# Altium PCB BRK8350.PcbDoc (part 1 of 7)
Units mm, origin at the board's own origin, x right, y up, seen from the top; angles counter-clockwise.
Board outline 240 x 150 mm, 8 copper layers (L1-TOP, L2-GND, L3-PWR, L4-SIG, L5-SIG, L6-PWR, L7-GND, L8-BOT), stack 1.465 mm thick; 277 components, 542 nets, 1814 pads, 2338 vias.
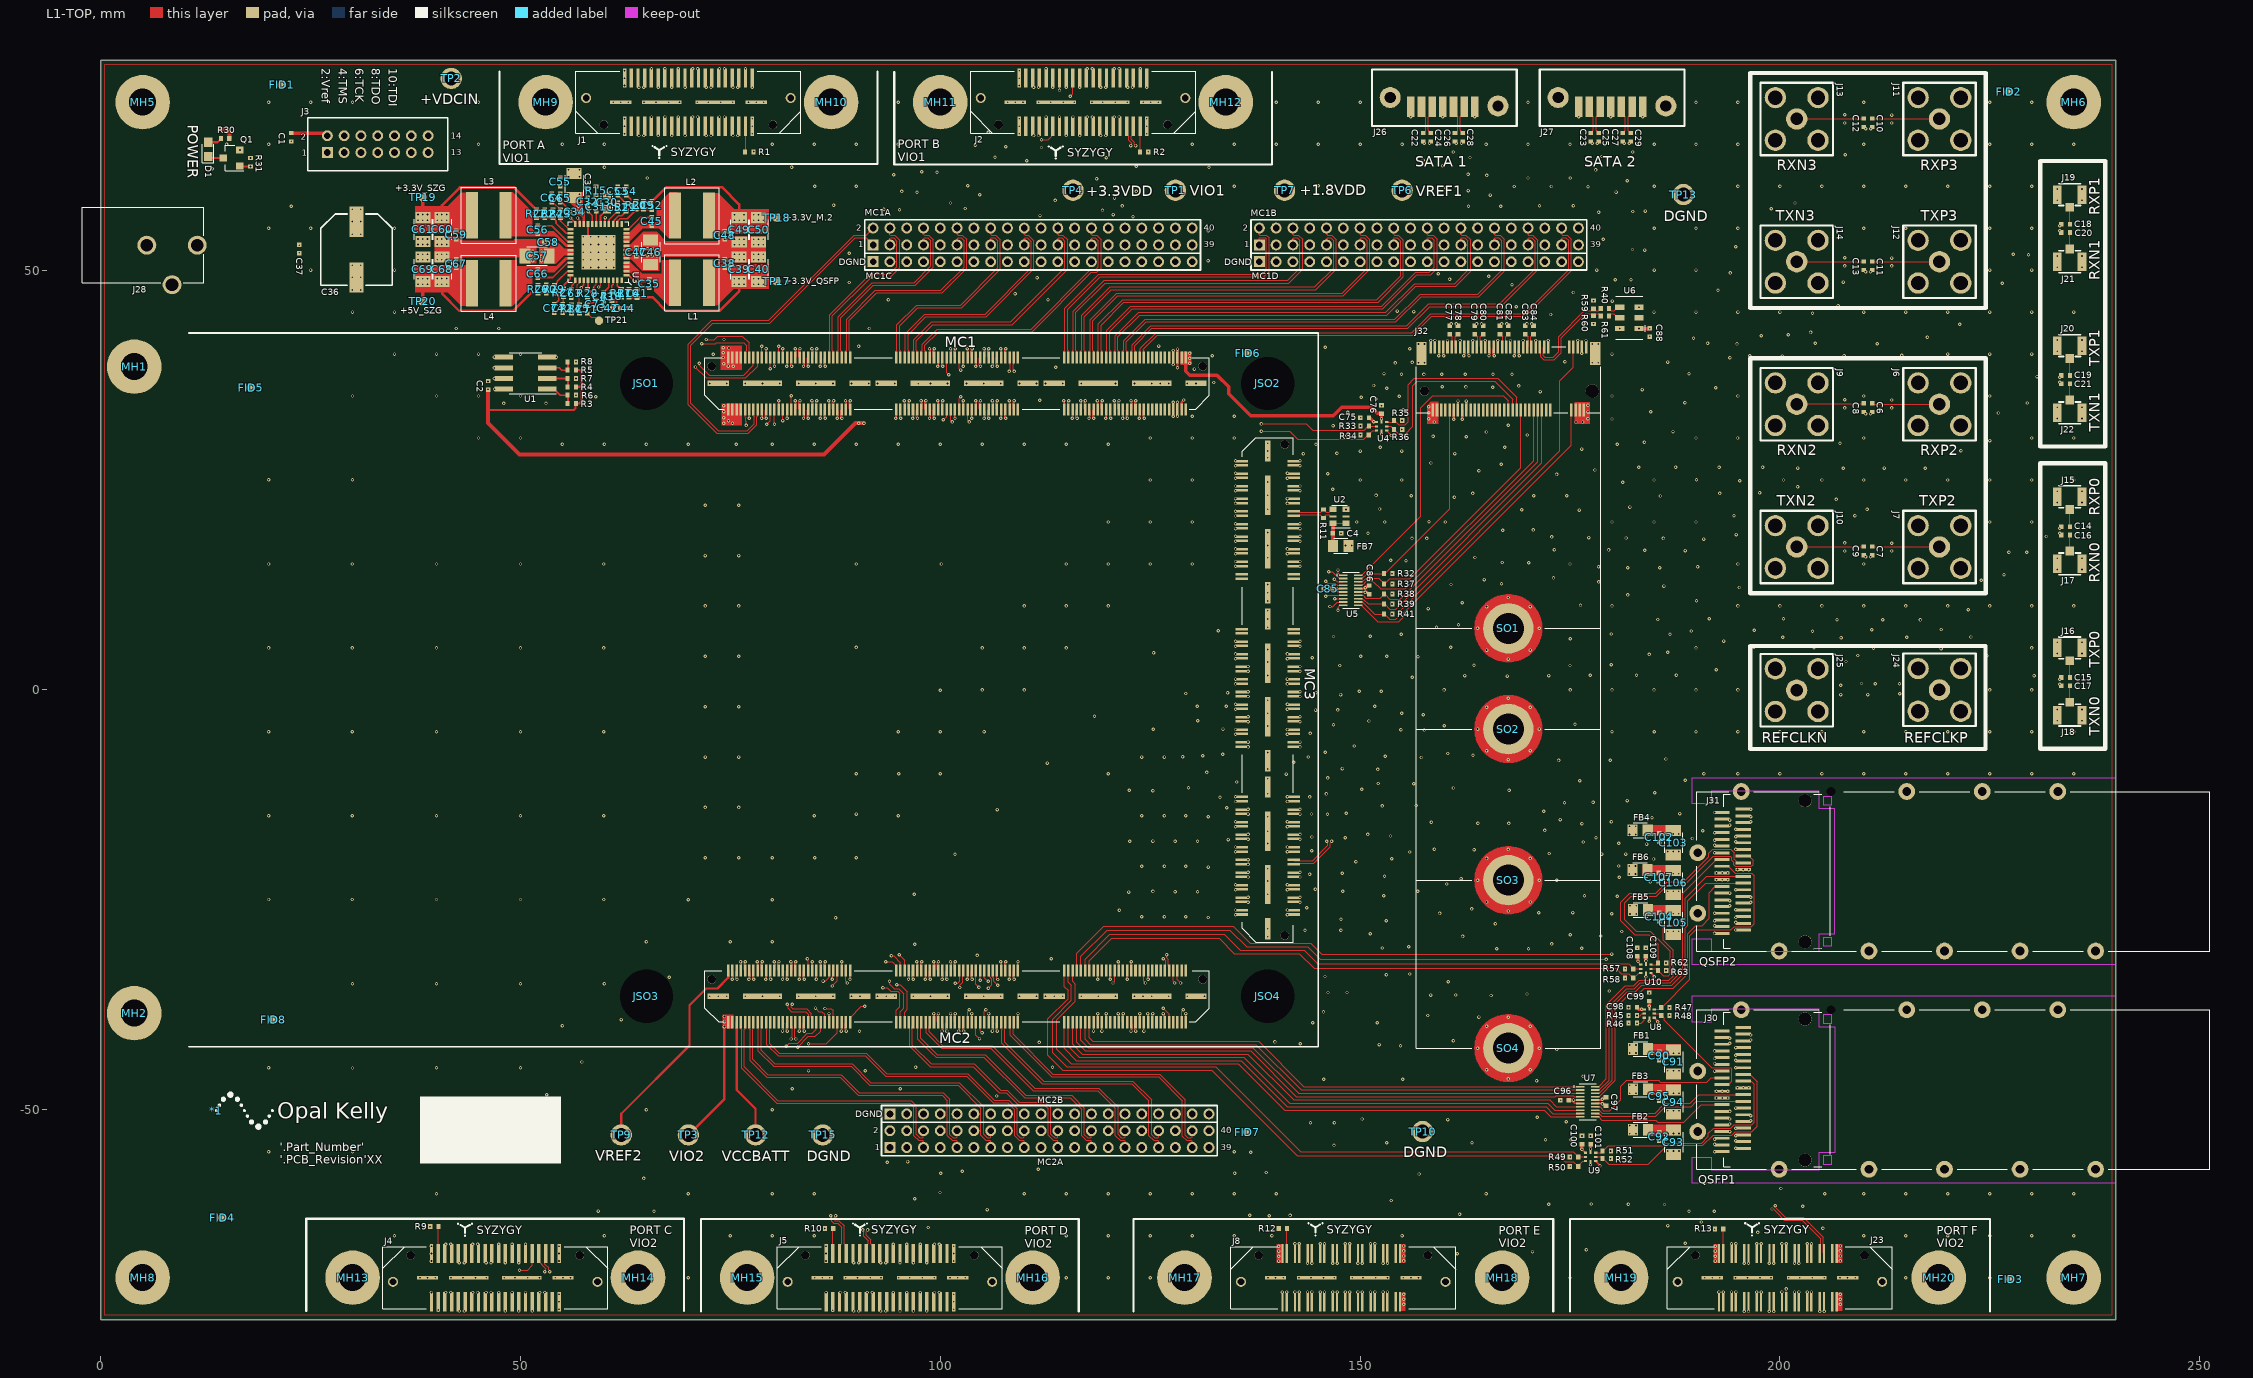
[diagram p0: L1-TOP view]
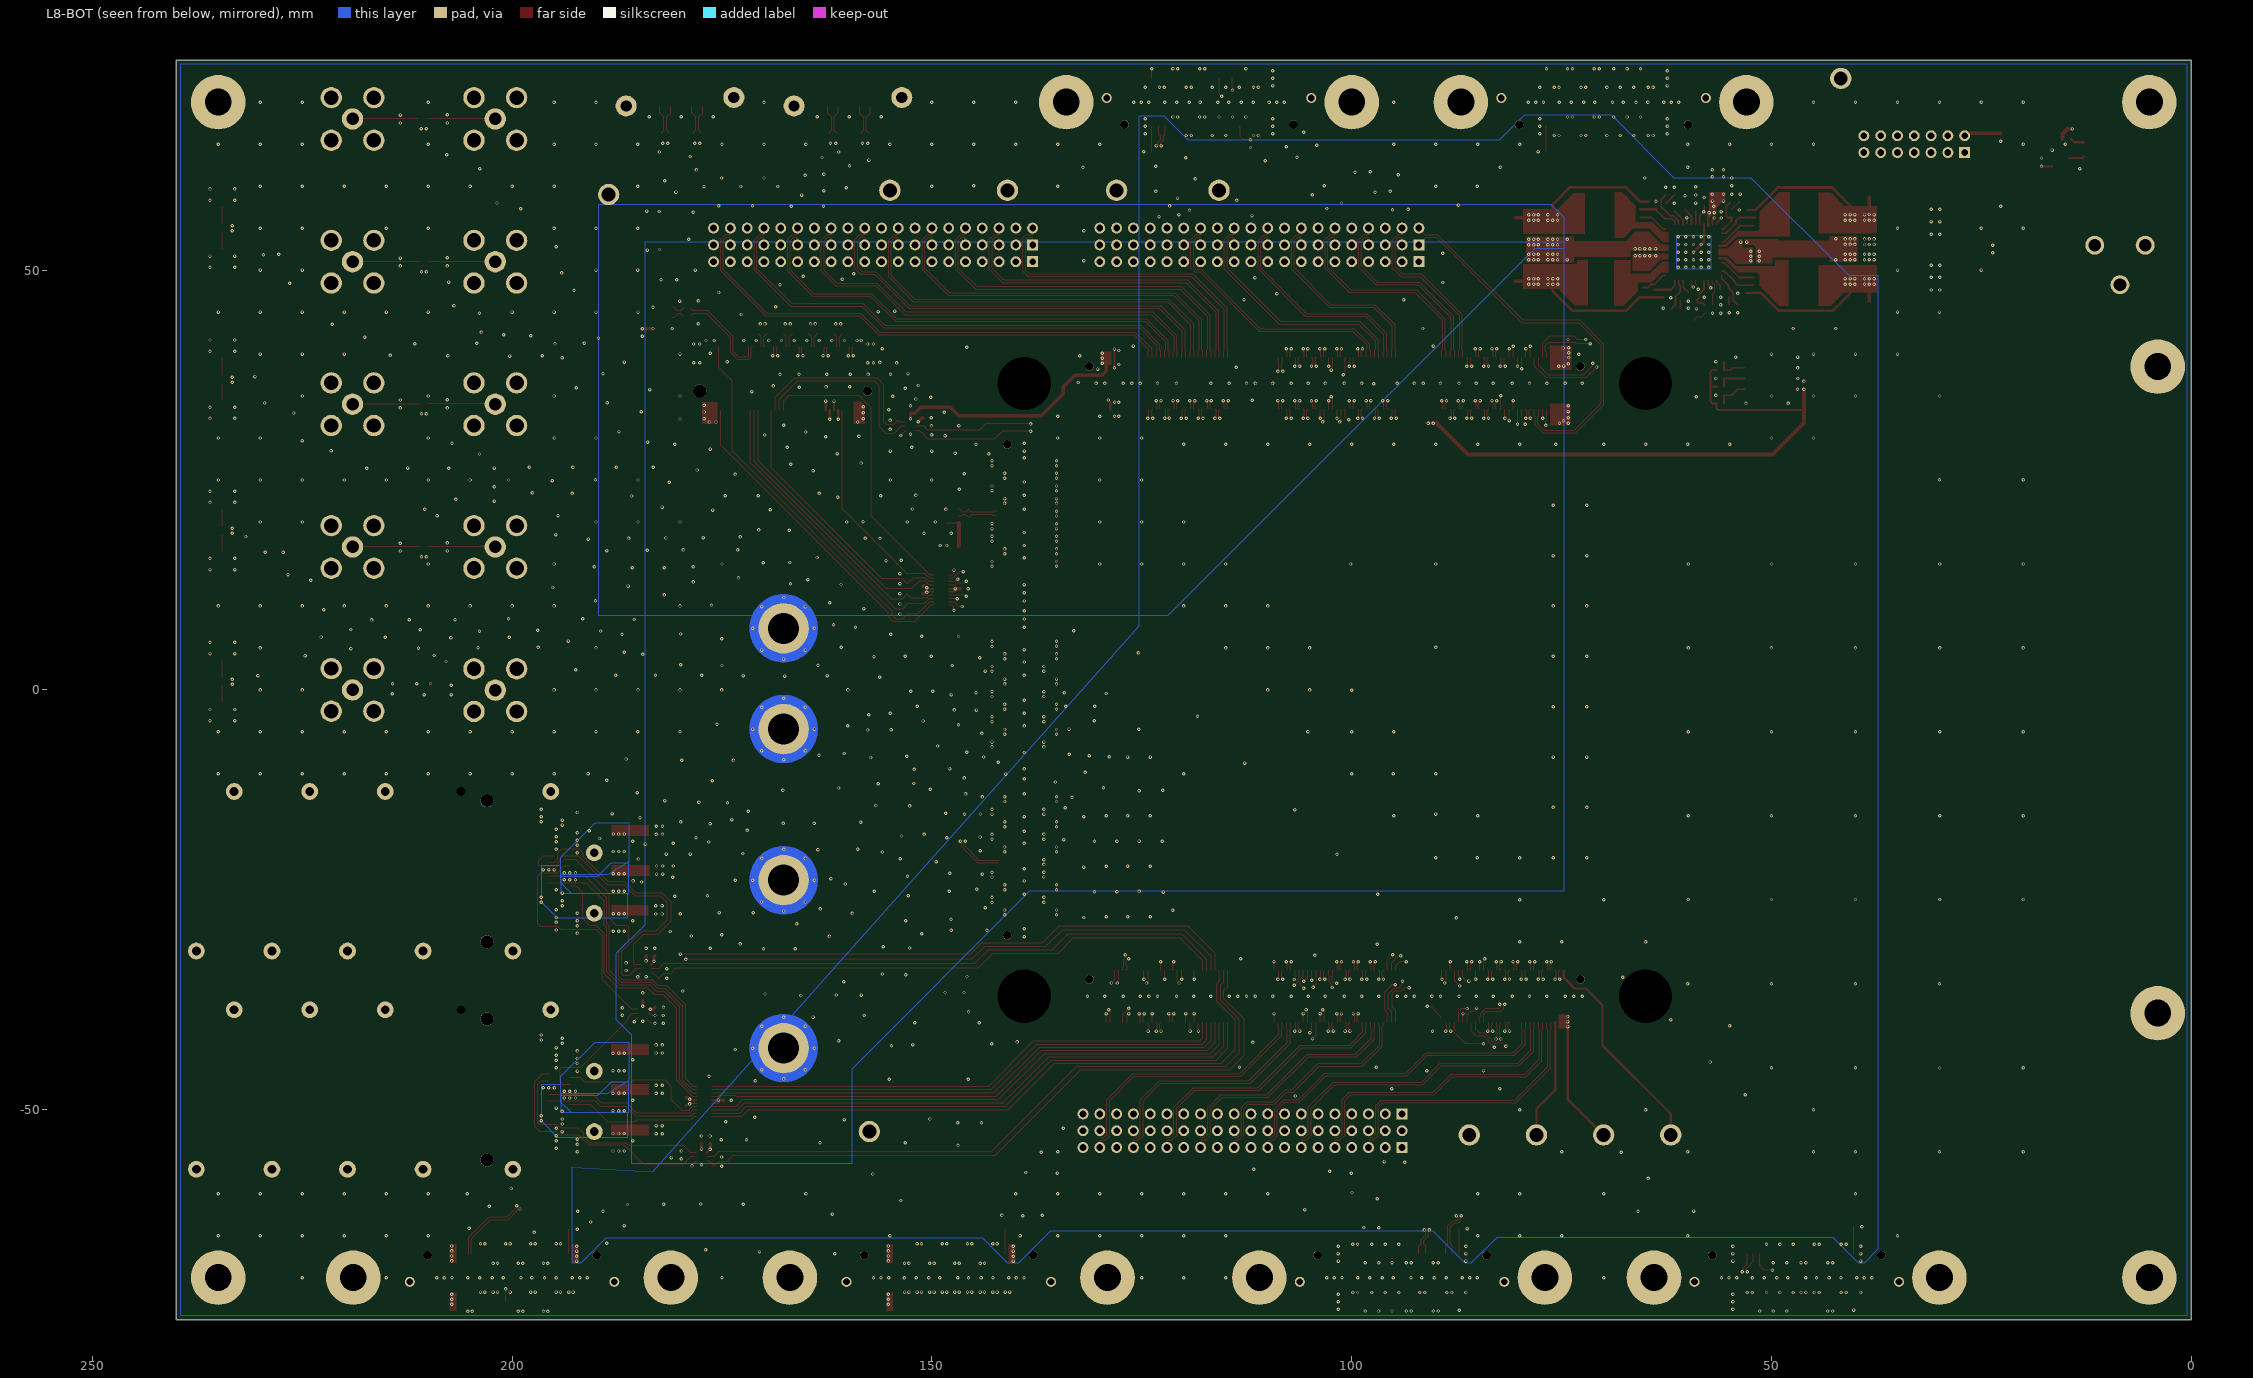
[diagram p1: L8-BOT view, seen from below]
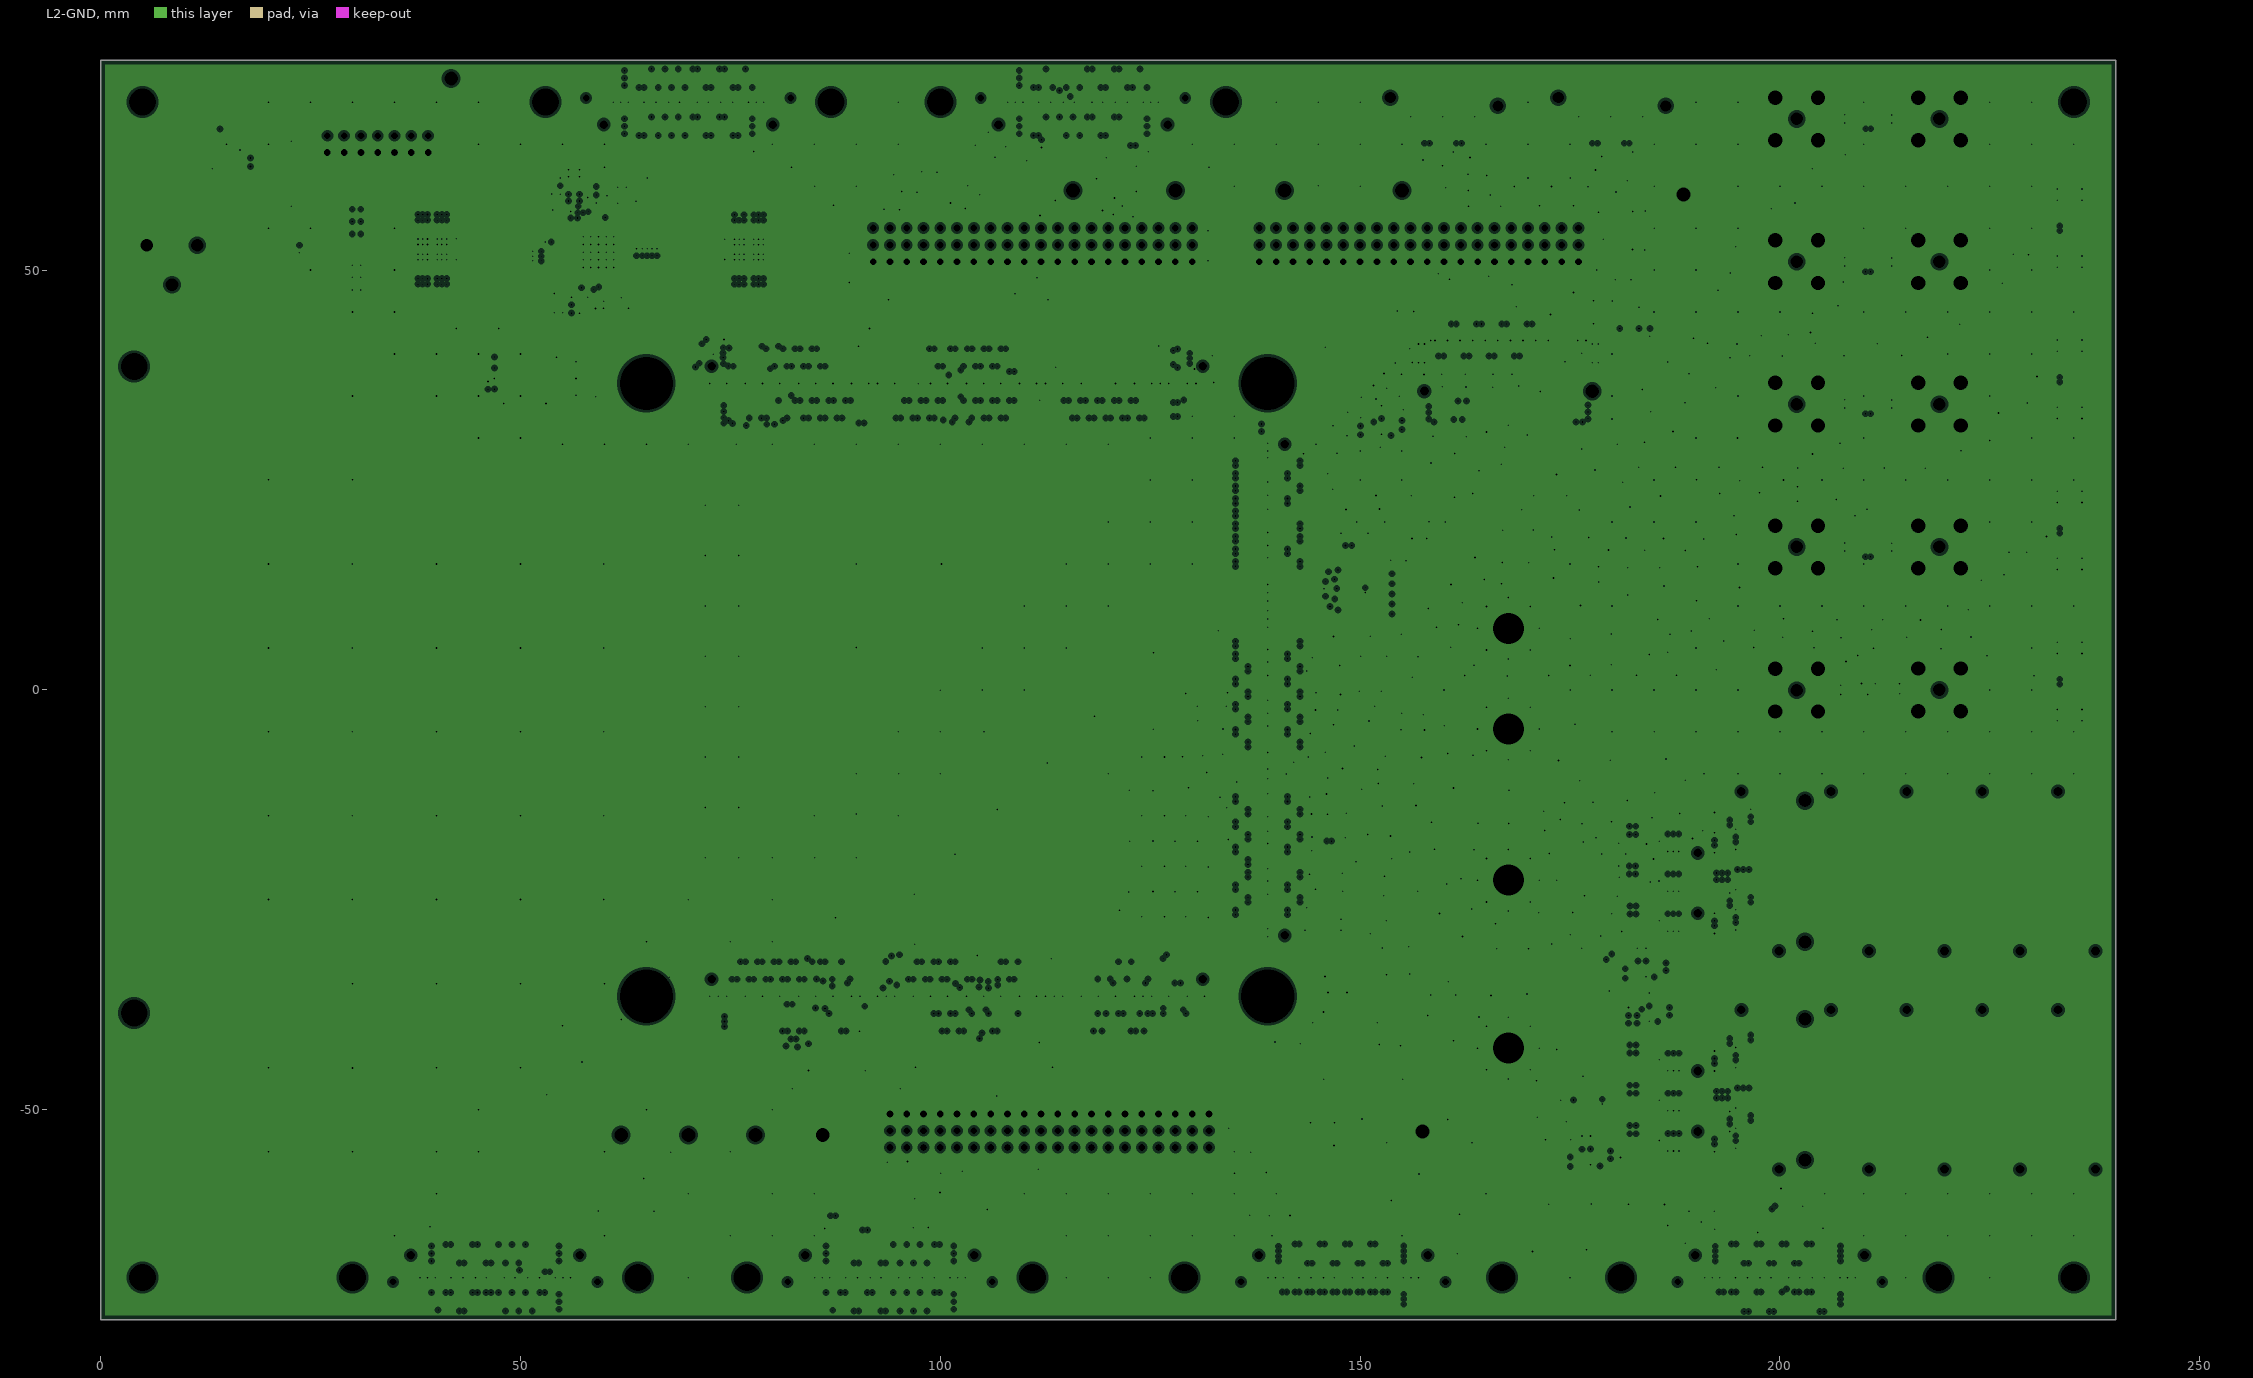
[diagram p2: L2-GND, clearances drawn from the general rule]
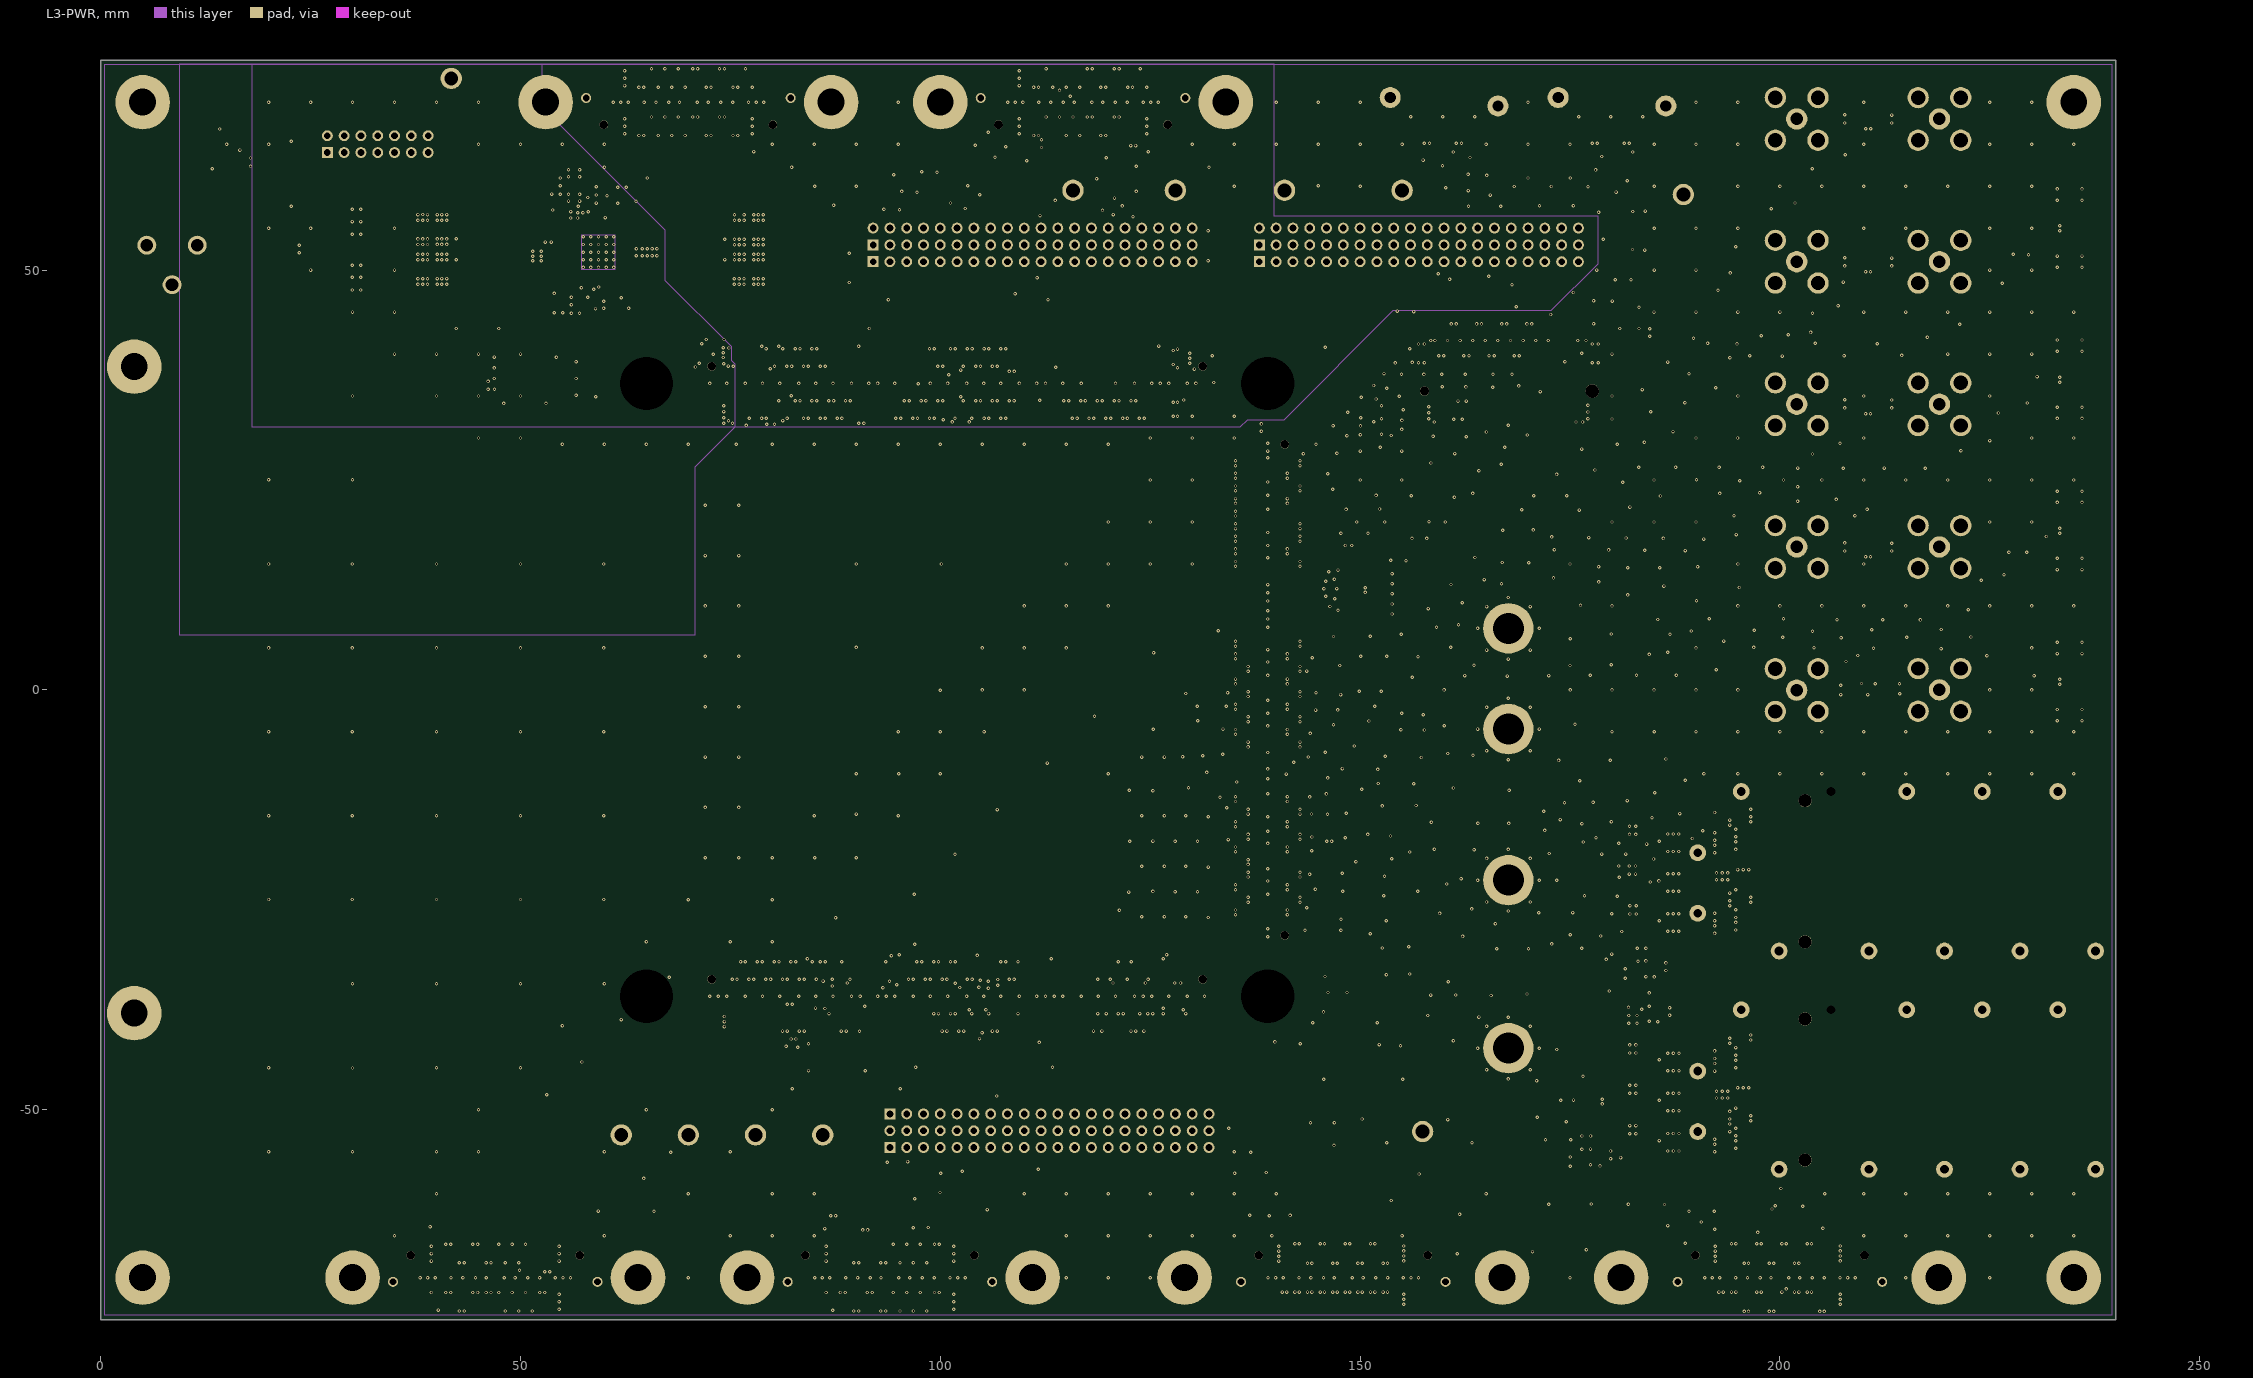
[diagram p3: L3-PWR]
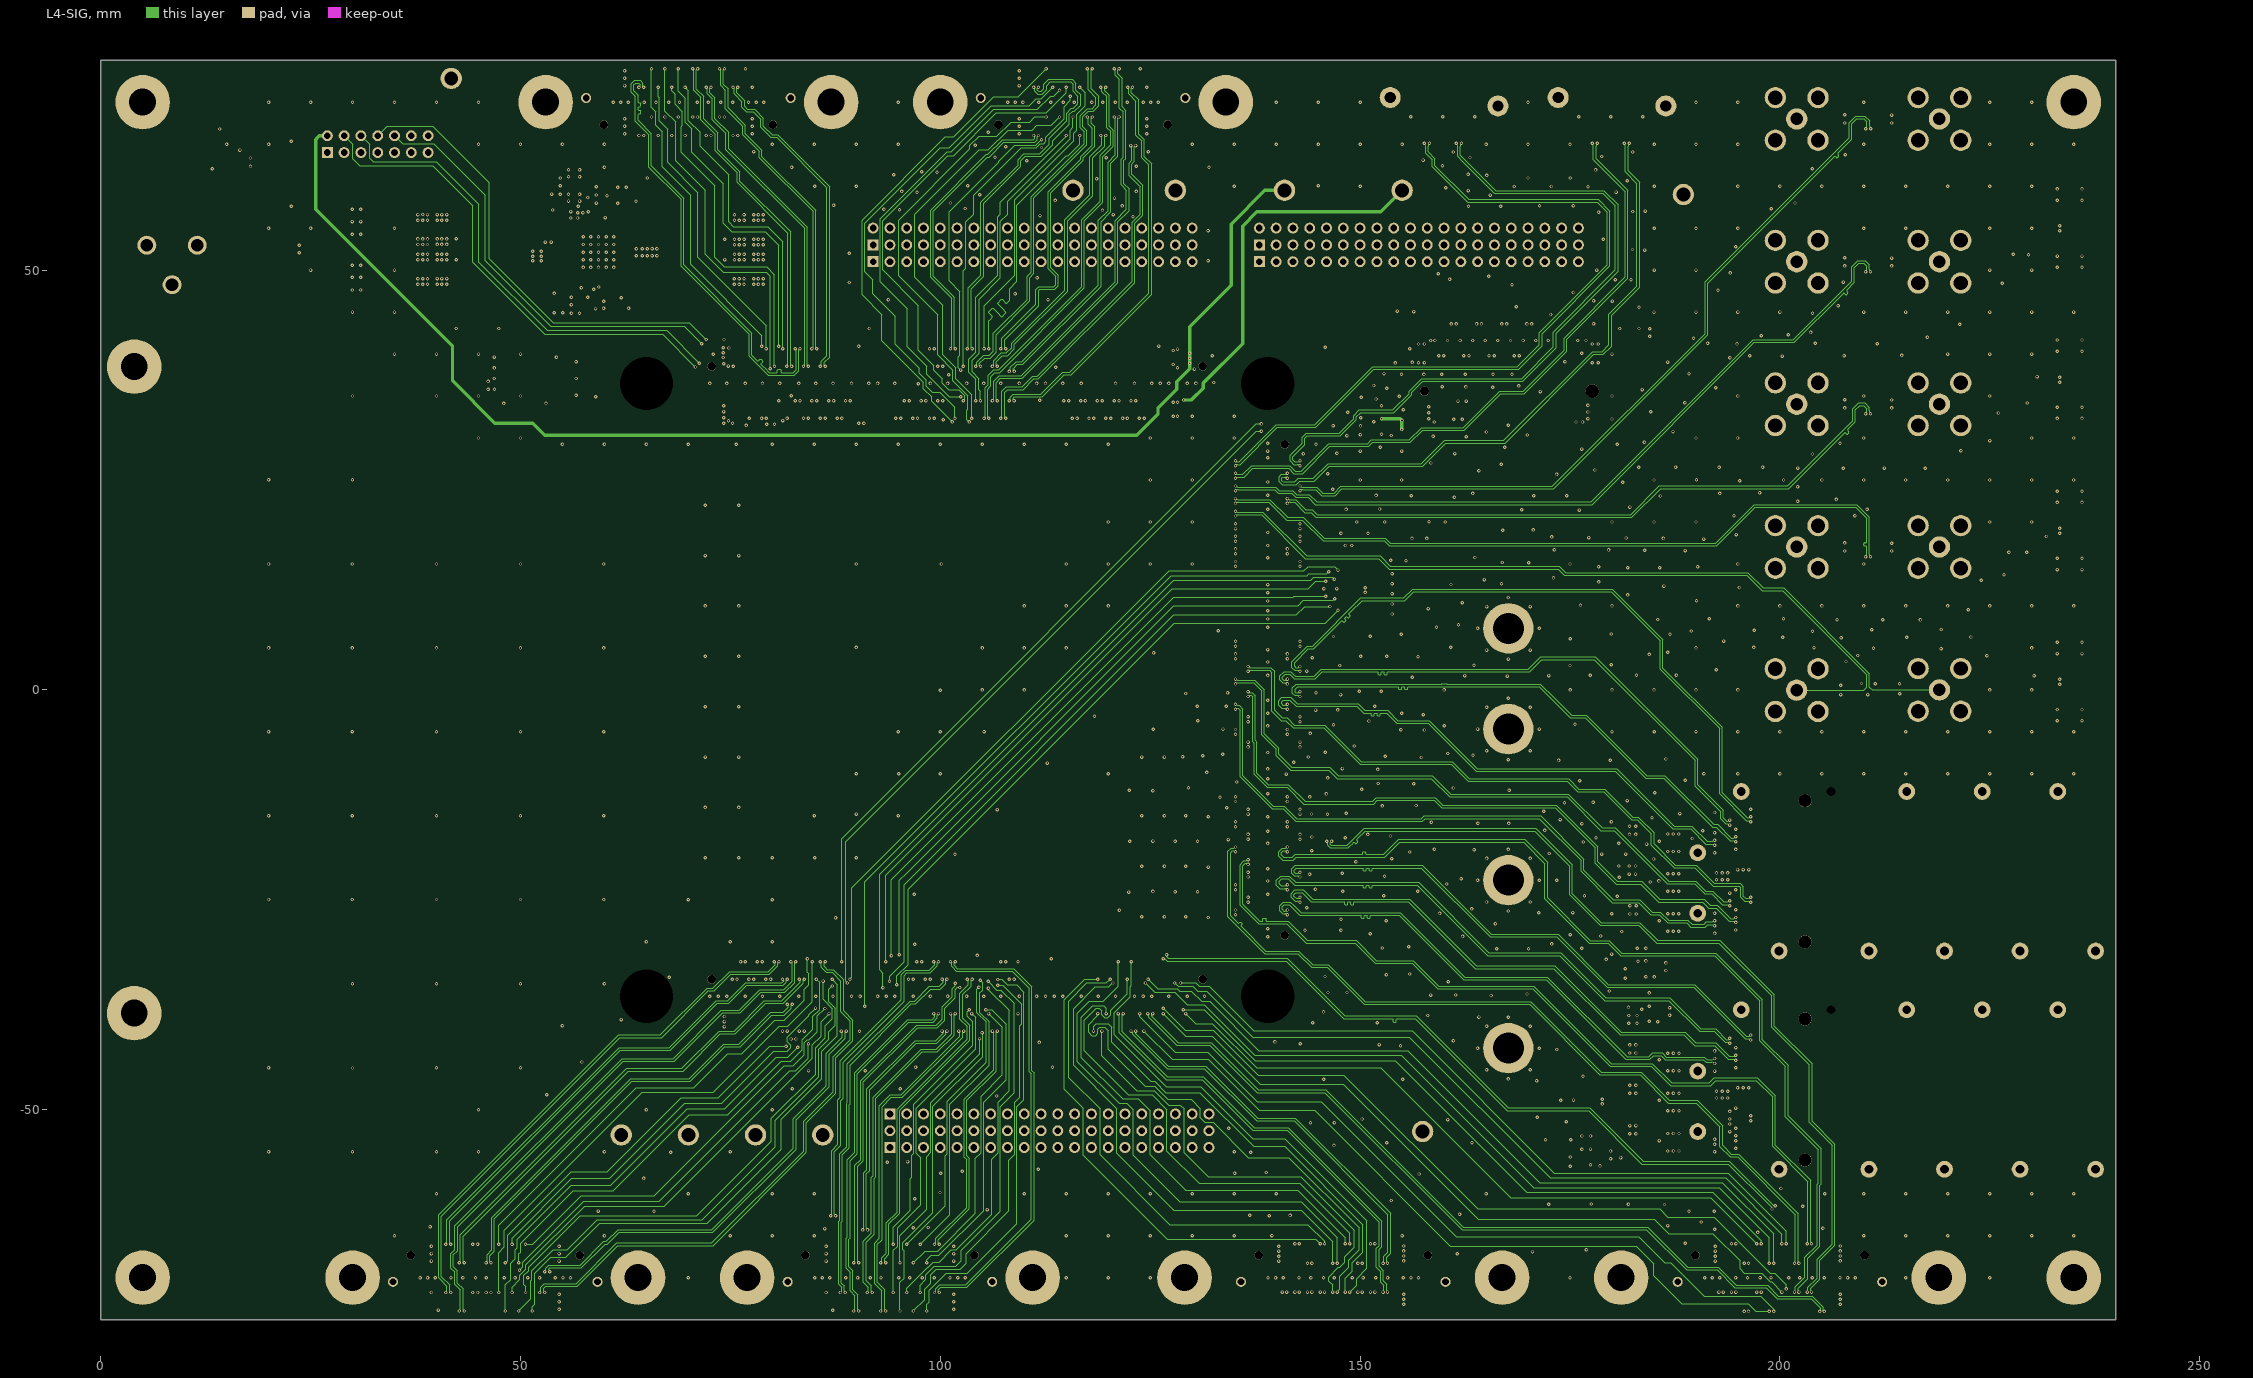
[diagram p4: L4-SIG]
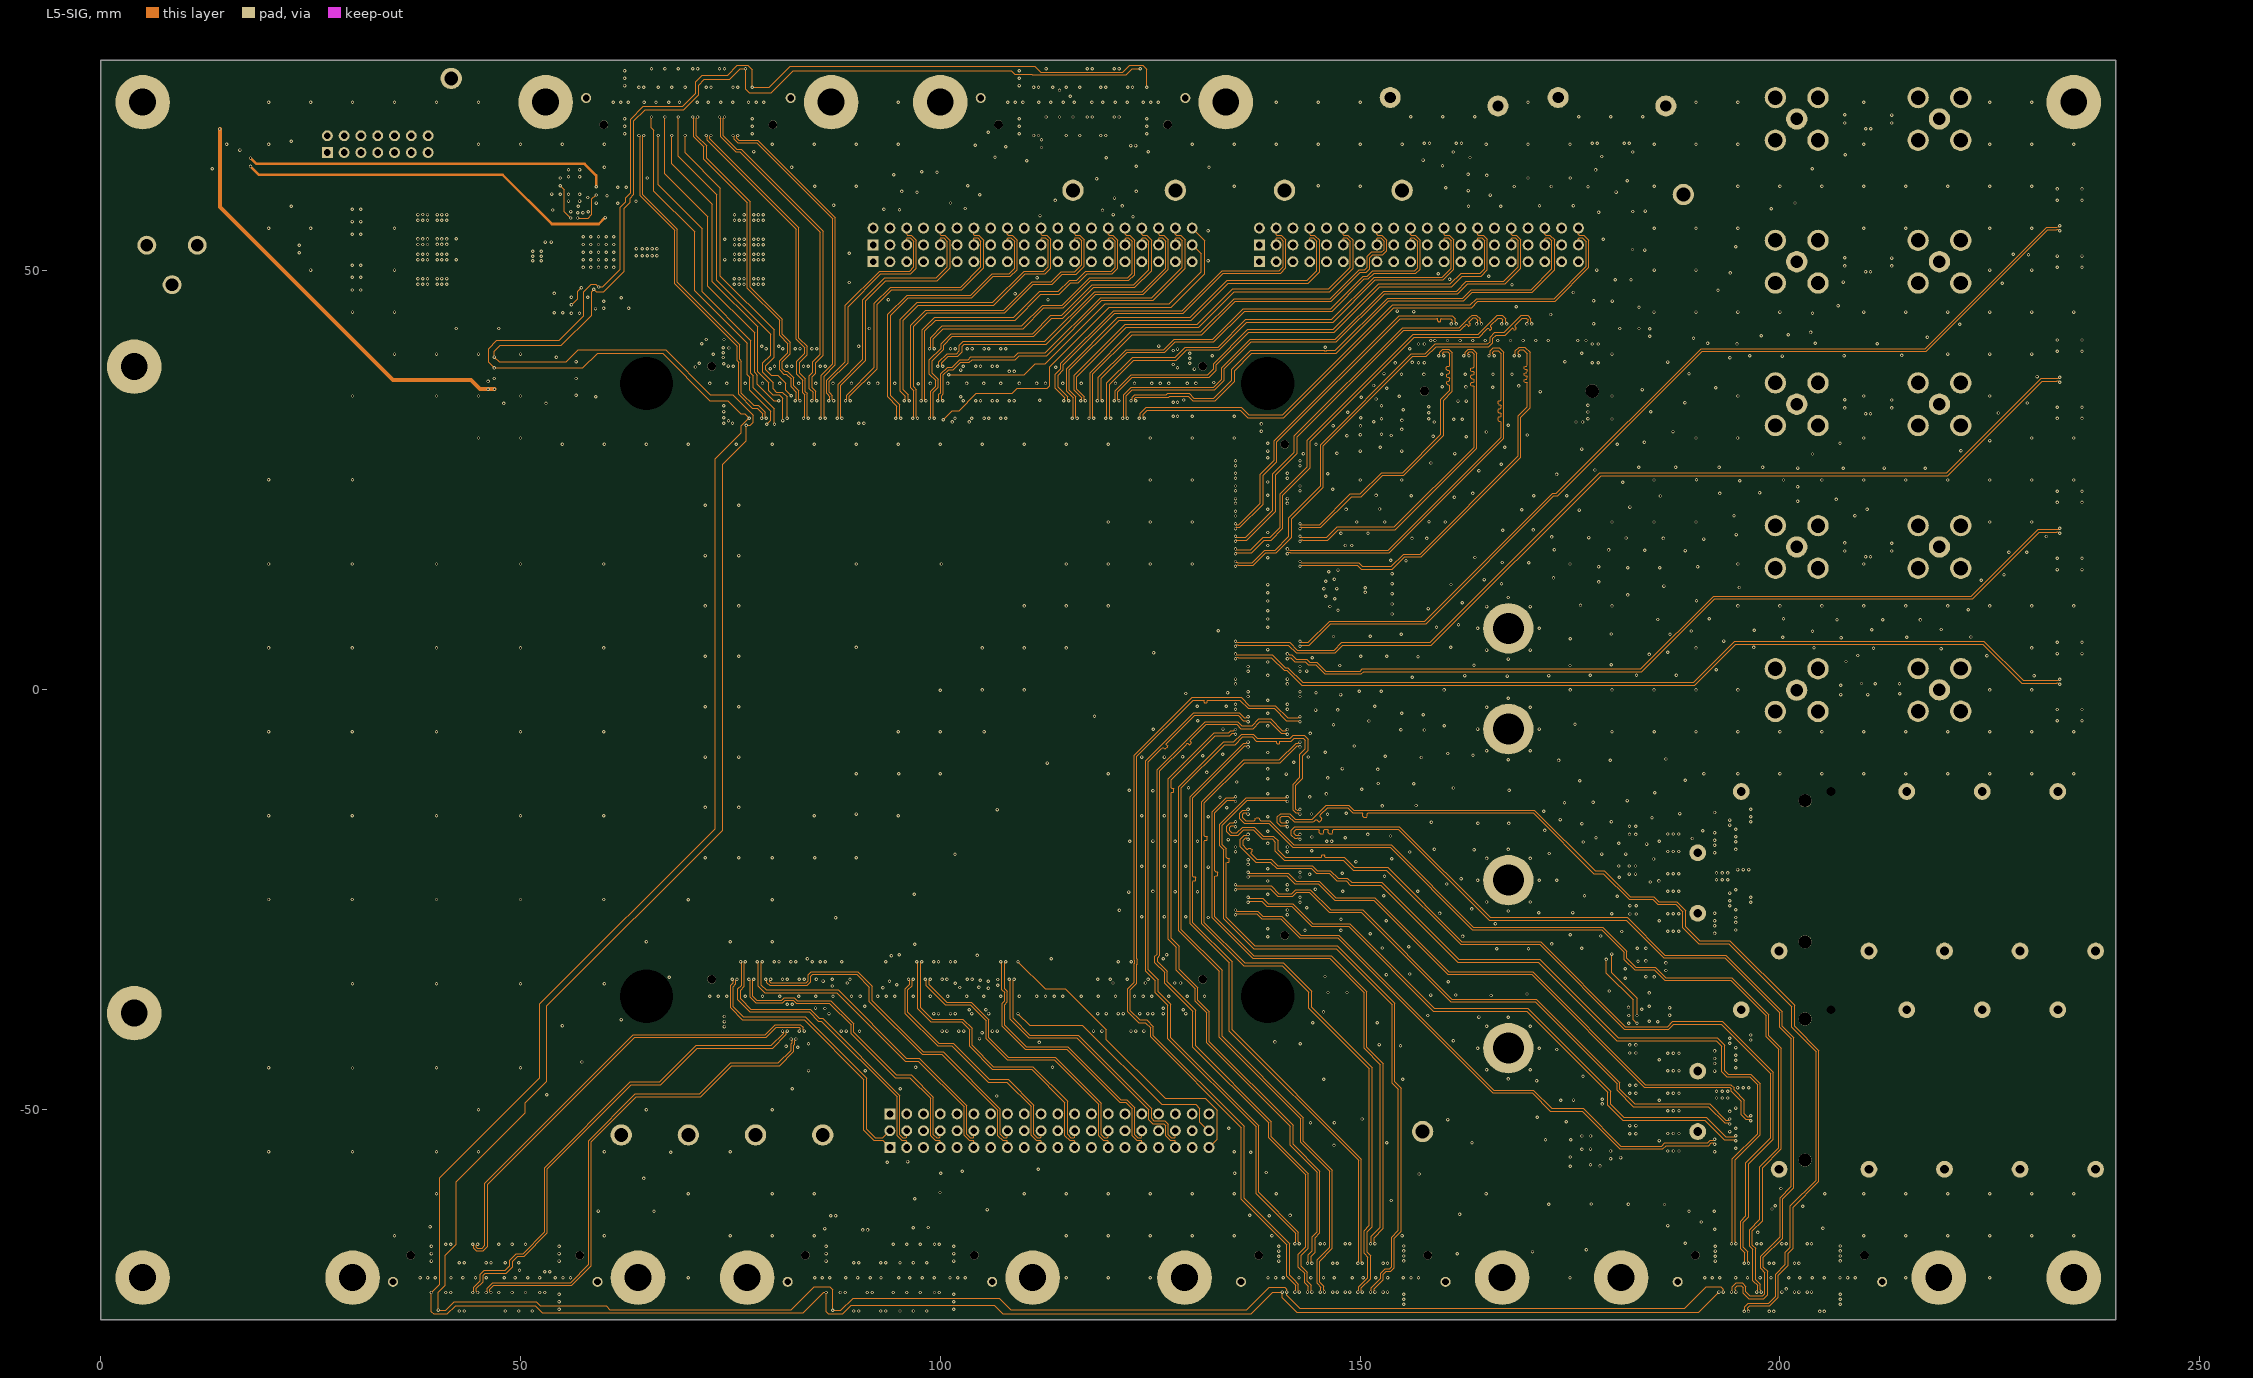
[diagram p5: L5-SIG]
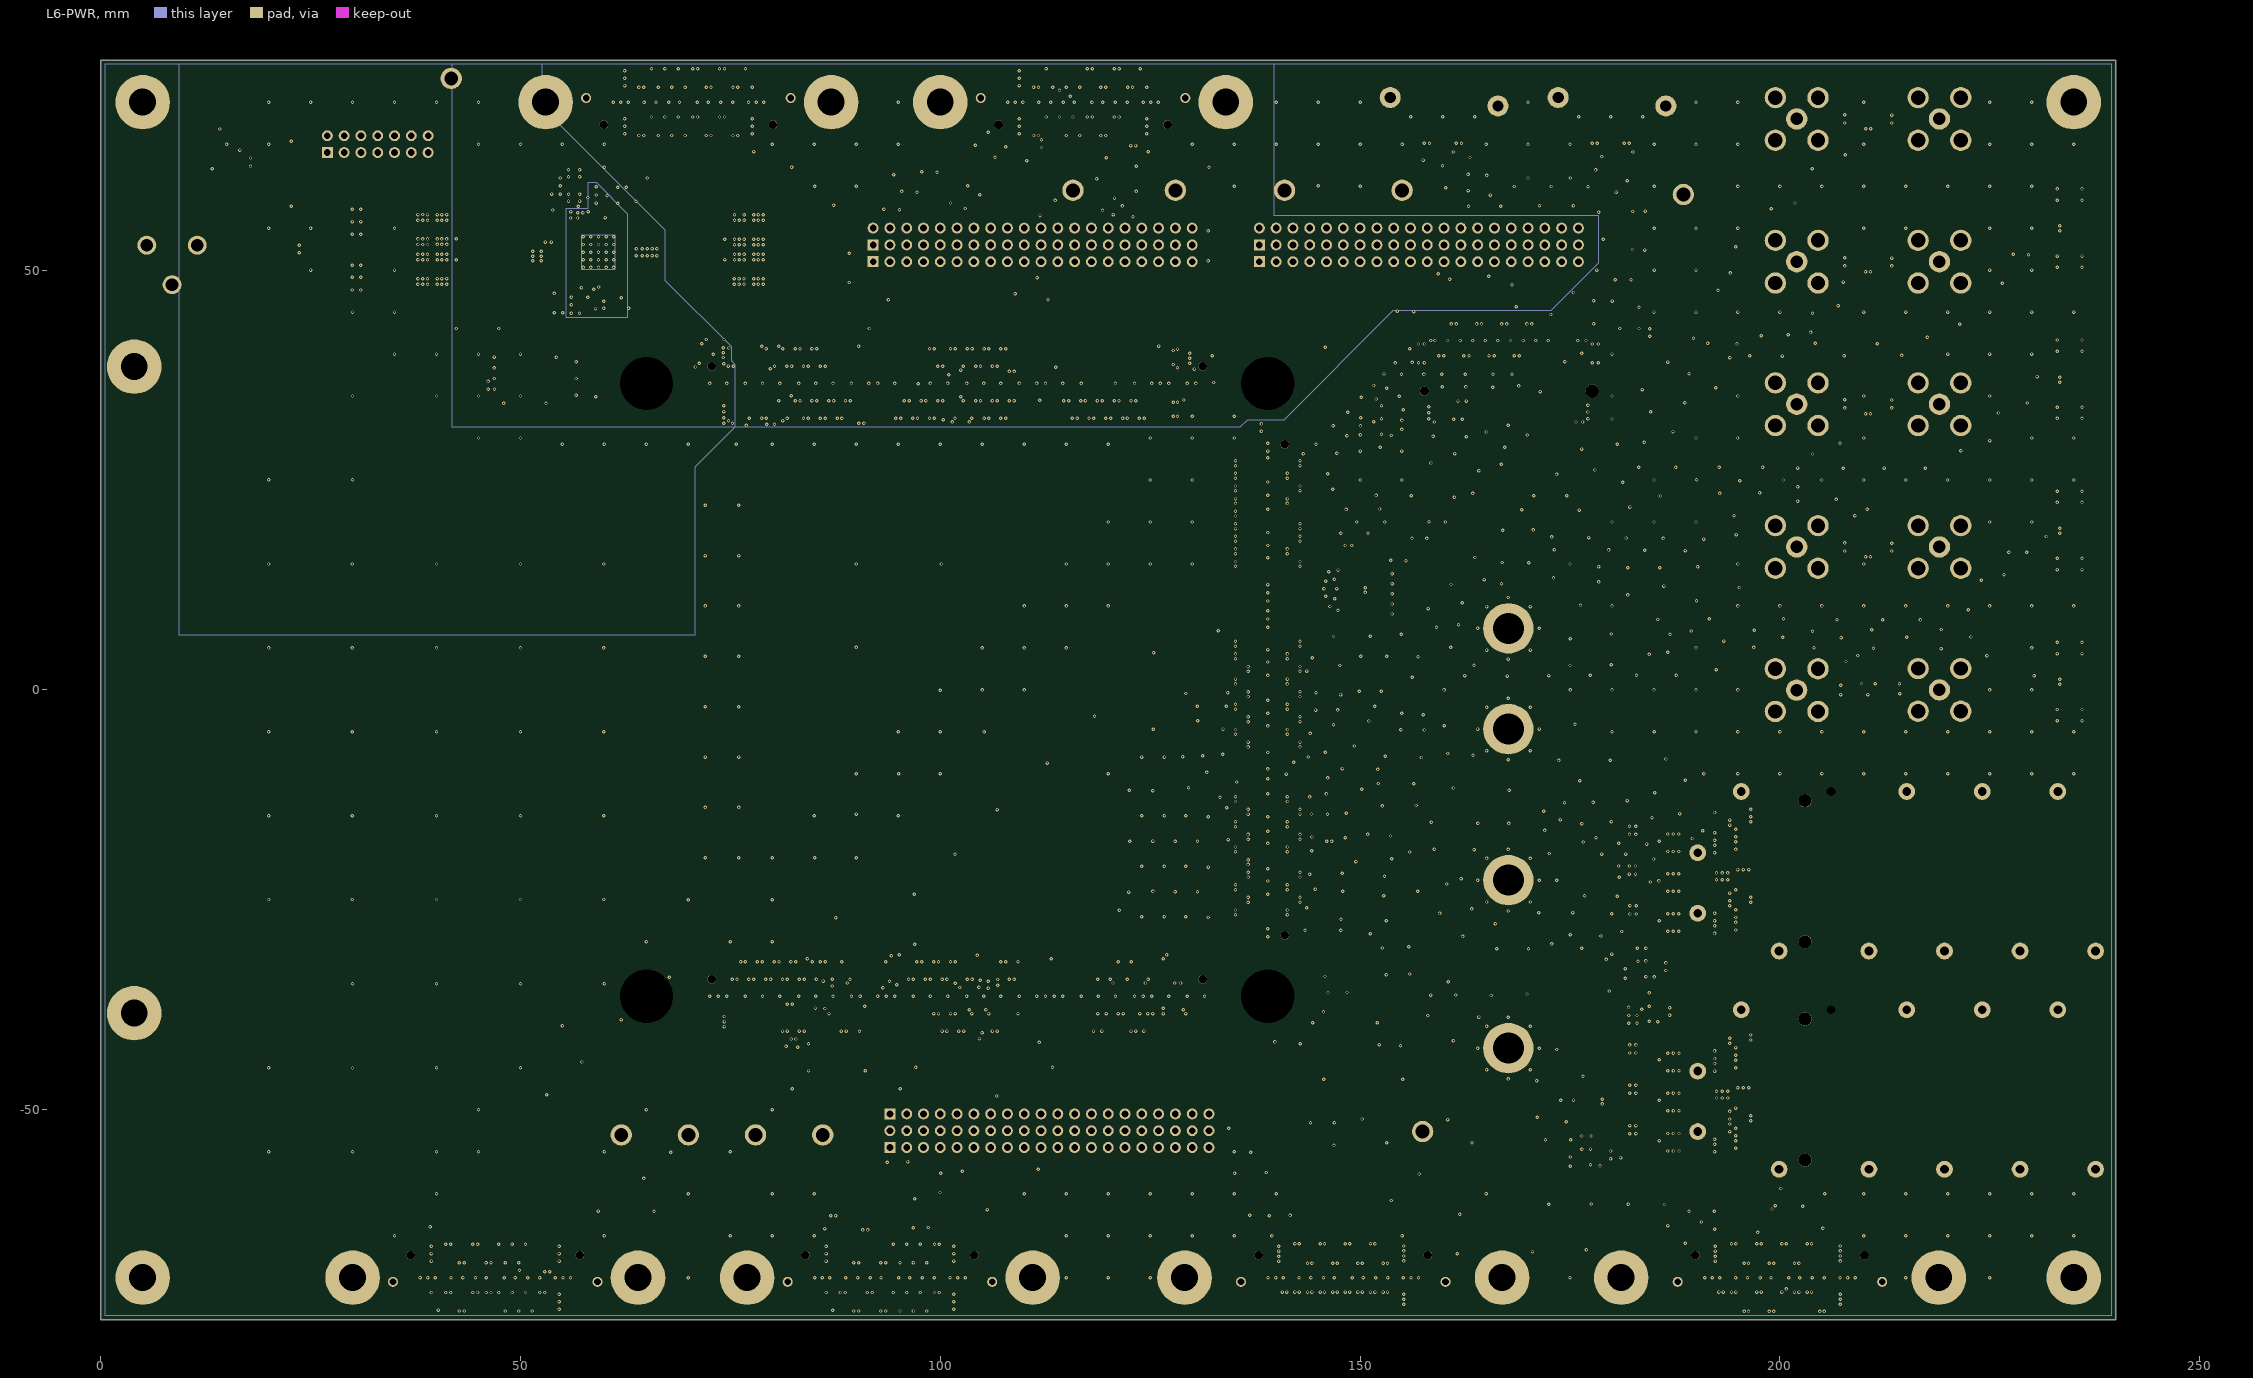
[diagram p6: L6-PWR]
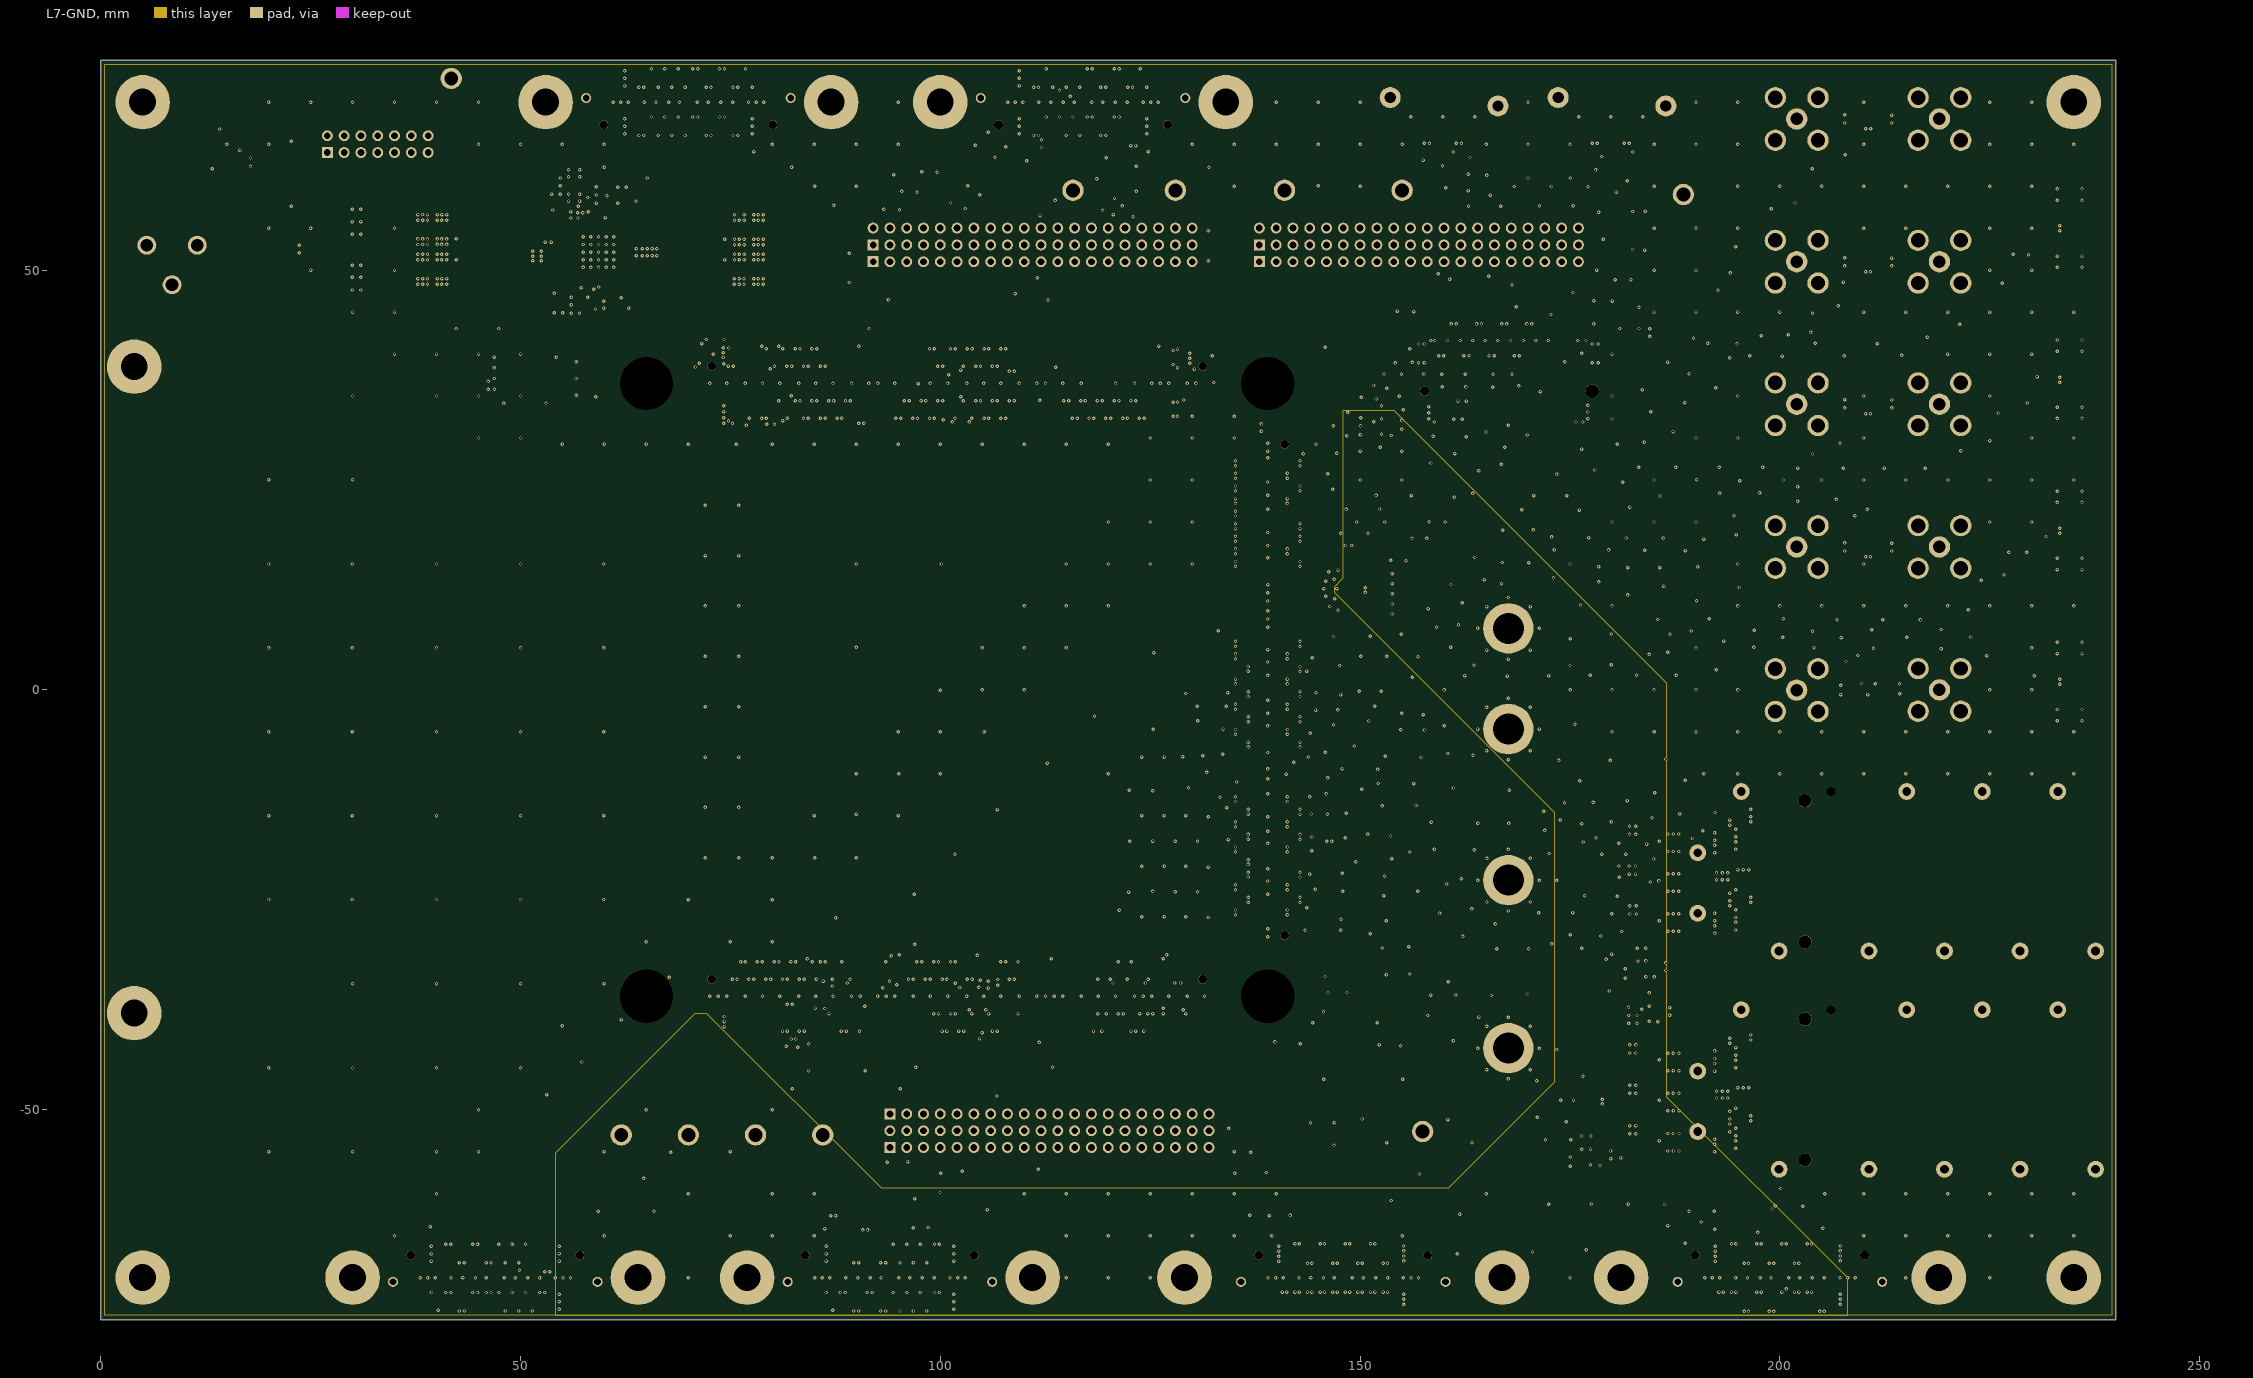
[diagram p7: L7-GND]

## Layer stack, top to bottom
Top Solder: solder mask 0.0203, Solder Resist, Dk 0
L1-TOP: signal copper 0.0356
Dielectric 2: prepreg 0.081, IT180A, Dk 3.79
L2-GND: plane copper 0.0356, net DGND
Dielectric 1: core 0.2644, IT180A, Dk 4.35
L3-PWR: signal copper 0.0356
Dielectric 3: prepreg 0.095, IT180A, Dk 3.61
L4-SIG: signal copper 0.0356
Dielectric 5: core 0.3, IT180A, Dk 4.35
L5-SIG: signal copper 0.0356
Dielectric 6: prepreg 0.095, IT180A, Dk 3.61
L6-PWR: signal copper 0.0356
Dielectric 7: core 0.2644, IT180A, Dk 4.35
L7-GND: signal copper 0.0356
Dielectric 4: prepreg 0.081, IT180A, Dk 3.79
L8-BOT: signal copper 0.0356
Solder Side: solder mask 0.0203, Solder Resist, Dk 0

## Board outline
0,-75 0,75 240,75 240,-75

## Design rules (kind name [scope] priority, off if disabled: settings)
Clearance [All] p1: gap=0.127 ignorepadtopadclearanceinfootprint=FALSE except(0.114: SMDPad-Via Via-Via; 0.203: Arc-Poly SMDPad-Poly THPad-Poly Via-Fill Via-Poly Via-Region Fill-Poly Poly-Region Poly-Text Poly-Hole; 0.254: Track-Poly; 0.381: Poly-Poly)
DiffPairsRouting 100ohm_Diff [InDifferentialPairClass('100ohm_Diff')] p1: maxlimit=0.254 minlimit=0.213 mostfreqgap=0.254 toplayer_maxgap=0.213 toplayer_prefgap=0.213 toplayer_minwidth=0.107 toplayer_maxwidth=0.107 toplayer_prefwidth=0.107 midlayer1_mingap=0.254 midlayer1_minwidth=0.381 midlayer1_maxwidth=0.381 midlayer1_prefwidth=0.381 midlayer2_maxgap=0.213 midlayer2_prefgap=0.213 midlayer2_minwidth=0.107 midlayer2_maxwidth=0.107 midlayer2_prefwidth=0.107 midlayer3_maxgap=0.213 midlayer3_prefgap=0.213 midlayer3_minwidth=0.107 midlayer3_maxwidth=0.107 midlayer3_prefwidth=0.107 midlayer4_mingap=0.254 midlayer4_minwidth=0.381 midlayer4_maxwidth=0.381 midlayer4_prefwidth=0.381 midlayer5_mingap=0.254 midlayer5_minwidth=0.381 midlayer5_maxwidth=0.381 midlayer5_prefwidth=0.381 bottomlayer_maxgap=0.213 bottomlayer_prefgap=0.213 bottomlayer_minwidth=0.107 bottomlayer_maxwidth=0.107 bottomlayer_prefwidth=0.107 maxuncoupledlength=8.89
FabricationTestPointUsage TestPointUsage [All] p1: valid=0 allowmultiple=FALSE
FabricationTestpoint Testpoint [All] p1: side=3 testpointundercomponent=TRUE minsize=1.016 maxsize=2.54 preferedsize=1.524 minholesize=0 maxholesize=1.016 preferedholesize=0.813 testpointgrid=0.025 allowsidetop=TRUE allowsidebottom=TRUE usegrid=TRUE gridtolerance=0
HoleSize [All] p1: absolutevalues=TRUE maxlimit=12.7 minlimit=0.203 maxpercent=80.000 minpercent=20.000
MatchedLengths okMatched_PortA [InxSignalClass('xSignals_PORTA')] p1: tolerance=25.4 checknetsindiffpair=FALSE checkdiffpairvsdiffpair=TRUE checkxsignals=TRUE checkothers=TRUE
MatchedLengths okMatched_PortB [InxSignalClass('xSignals_PORTB')] p2: tolerance=25.4 checknetsindiffpair=FALSE checkdiffpairvsdiffpair=TRUE checkxsignals=TRUE checkothers=TRUE
MatchedLengths okMatched_PortC [InxSignalClass('xSignals_PORTC')] p3: tolerance=25.4 checknetsindiffpair=FALSE checkdiffpairvsdiffpair=TRUE checkxsignals=TRUE checkothers=TRUE
MatchedLengths okMatched_PortD [InxSignalClass('xSignals_PORTD')] p4: tolerance=25.4 checknetsindiffpair=FALSE checkdiffpairvsdiffpair=TRUE checkxsignals=TRUE checkothers=TRUE
MatchedLengths okMatched_PortE [InxSignalClass('xSignals_PORTE')] p5: tolerance=25.4 checknetsindiffpair=FALSE checkdiffpairvsdiffpair=TRUE checkxsignals=TRUE checkothers=TRUE
MatchedLengths okMatched_PortF [InxSignalClass('xSignals_PORTF')] p6: tolerance=25.4 checknetsindiffpair=FALSE checkdiffpairvsdiffpair=TRUE checkxsignals=TRUE checkothers=TRUE
MatchedLengths okMatched_100ohm_Diff [InxSignalClass('xSignals_100ohm_Diff')] p7: tolerance=0.127 checknetsindiffpair=TRUE checkdiffpairvsdiffpair=FALSE checkxsignals=FALSE checkothers=FALSE
MinimumAnnularRing [All] p1: minimumring=0.102
MinimumSolderMaskSliver [All] p1: minsoldermaskwidth=0.048
PlaneClearance [All] p1: clearance=0.305
PlaneConnect [All] p1: planeconnectstyle=Direct reliefexpansion=0.508 reliefentries=4 reliefconductorwidth=0.254 reliefairgap=0.254
PolygonConnect "Via Connect" [IsVia] p1: connectstyle=Direct reliefconductorwidth=0.254 reliefentries=4 polygonreliefangle="90 Angle" airgapwidth=0.254
PolygonConnect [All] p2: connectstyle=Direct reliefconductorwidth=0.305 reliefentries=4 polygonreliefangle="90 Angle" airgapwidth=0.254
RoutingVias [All] p1: holewidth=0.203 width=0.406 viastyle="Through Hole" minholewidth=0.203 minwidth=0.406 maxholewidth=1.27 maxwidth=2.54
SilkToSilkClearance [All] p1: silktosilkclearance=0.003
SilkToSolderMaskClearance SilkscreenOverComponentPads [IsPad] p1: minsilkscreentomaskgap=0.051 clearancetoexposedcopper=TRUE
SolderMaskExpansion [All] p1: expansion=0.051
Width okWidth_50ohm [InNetClass('50ohm')] p1: maxlimit=0.254 minlimit=0.114 preferedwidth=0.254 toplayer_maxwidth=0.114 toplayer_prefwidth=0.114 midlayer1_minwidth=0.254 midlayer2_minwidth=0.117 midlayer2_maxwidth=0.117 midlayer2_prefwidth=0.117 midlayer3_minwidth=0.117 midlayer3_maxwidth=0.117 midlayer3_prefwidth=0.117 midlayer4_minwidth=0.254 midlayer5_minwidth=0.254 bottomlayer_maxwidth=0.114 bottomlayer_prefwidth=0.114 minimp=50.000000 maximp=50.000000 favimp=50.000000
Width okWidth [All] p2: maxlimit=3.81 minlimit=0.102 preferedwidth=0.2 toplayer_prefwidth=0.127 midlayer1_prefwidth=0.127 midlayer2_prefwidth=0.127 midlayer3_prefwidth=0.127 midlayer4_prefwidth=0.127 midlayer5_minwidth=0.2 midlayer5_maxwidth=0.2 bottomlayer_prefwidth=0.127 minimp=50.000000 maximp=50.000000 favimp=50.000000
21 further rules are at their usual default settings.

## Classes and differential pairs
net class 50ohm: MC1A_3 MC1A_4 MC1A_5 MC1A_6 MC1A_7 MC1A_8 MC1A_9 MC1A_10 MC1A_11 MC1A_12 MC1A_13 MC1A_14 MC1A_15 MC1A_16 MC1A_17 MC1A_18 MC1A_19 MC1A_20 MC1A_21 MC1A_22 MC1A_23 MC1A_24 MC1A_25 MC1A_26 MC1A_27 MC1A_28 MC1A_29 MC1A_30 MC1A_31 MC1A_32 MC1A_33 MC1A_34 MC1A_35 MC1A_36 MC1A_37 MC1A_38 MC1A_39 MC1A_40 MC1B_1 MC1B_2 MC1B_3 MC1B_4 MC1B_5 MC1B_6 MC1B_7 MC1B_8 MC1B_9 MC1B_10 MC1B_11 MC1B_12 MC1B_13 MC1B_14 MC1B_15 MC1B_16 MC1B_17 MC1B_18 MC1B_19 MC1B_20 MC1B_21 MC1B_22 MC1B_23 MC1B_24 MC1B_25 MC1B_26 MC1B_27 MC1B_28 MC1B_29 MC1B_30 MC1B_31 MC1B_32 MC1B_33 MC1B_34 MC1B_35 MC1B_36 MC1B_37 MC1B_38 MC1B_39 MC1B_40 MC2A_1 MC2A_2 MC2A_3 MC2A_4 MC2A_5 MC2A_6 MC2A_7 MC2A_8 MC2A_9 MC2A_10 MC2A_11 MC2A_12 MC2A_13 MC2A_14 MC2A_15 MC2A_16 MC2A_17 MC2A_18 MC2A_19 MC2A_20 MC2A_21 MC2A_22 MC2A_23 MC2A_24 MC2A_25 MC2A_26 MC2A_27 MC2A_28 MC2A_29 MC2A_30 MC2A_31 MC2A_32 MC2A_33 MC2A_34 MC2A_35 MC2A_36 MC2A_37 MC2A_38 MC2A_39 MC2A_40 PORTA_S16 PORTA_S17 PORTA_S18 PORTA_S19 PORTA_S20 PORTA_S21 PORTA_S22 PORTA_S23 PORTA_S24 PORTA_S25 PORTA_S26 PORTA_S27 PORTB_S16 PORTB_S17 PORTB_S18 PORTB_S19 PORTB_S20 PORTB_S21 PORTB_S22 PORTB_S23 PORTB_S24 PORTB_S25 PORTB_S26 PORTB_S27 PORTC_S16 PORTC_S17 PORTC_S18 PORTC_S19 PORTC_S20 PORTC_S21 PORTC_S22 PORTC_S23 PORTC_S24 PORTC_S25 PORTC_S26 PORTC_S27 PORTD_S16 PORTD_S17 PORTD_S18 PORTD_S19 PORTD_S20 PORTD_S21 PORTD_S22 PORTD_S23 PORTD_S24 PORTD_S25 PORTD_S26 PORTD_S27 PORTE_S0 PORTE_S1 PORTE_S2 PORTE_S3 PORTE_S4 PORTE_S5 PORTE_S6 PORTE_S7 PORTE_S8 PORTE_S9 PORTF_S0 PORTF_S1 PORTF_S2 PORTF_S3 PORTF_S4 PORTF_S5 PORTF_S6 PORTF_S7 PORTF_S8 PORTF_S9
net class Power: +1.8VDD +3.3V_M.2 +3.3V_QSFP +3.3V_SZG +3.3VDD +5V_SZG +VDCIN VCCBATT VDDD VIO1 VIO2
net class SMA: SMA_REFCLKN SMA_REFCLKP
net class QSFP_CONTROL: QSFP_1_INT_B QSFP_1_INT_B_3V3 QSFP_1_LP_MODE QSFP_1_LP_MODE_3V3 QSFP_1_MODPRS_B QSFP_1_MODPRS_B_3V3 QSFP_1_MODSEL_B QSFP_1_MODSEL_B_3V3 QSFP_1_RESET_B QSFP_1_RESET_B_3V3 QSFP_1_SCL QSFP_1_SCL_3V3 QSFP_1_SDA QSFP_1_SDA_3V3 QSFP_2_INT_B QSFP_2_INT_B_3V3 QSFP_2_LP_MODE QSFP_2_LP_MODE_3V3 QSFP_2_MODPRS_B QSFP_2_MODPRS_B_3V3 QSFP_2_MODSEL_B QSFP_2_MODSEL_B_3V3 QSFP_2_RESET_B QSFP_2_RESET_B_3V3 QSFP_2_SCL QSFP_2_SCL_3V3 QSFP_2_SDA QSFP_2_SDA_3V3
net class QSFP_TRANSCEIVER: QSFP_1_RX1N QSFP_1_RX1P QSFP_1_RX2N QSFP_1_RX2P QSFP_1_RX3N QSFP_1_RX3P QSFP_1_RX4N QSFP_1_RX4P QSFP_1_TX1N QSFP_1_TX1P QSFP_1_TX2N QSFP_1_TX2P QSFP_1_TX3N QSFP_1_TX3P QSFP_1_TX4N QSFP_1_TX4P QSFP_2_RX1N QSFP_2_RX1P QSFP_2_RX2N QSFP_2_RX2P QSFP_2_RX3N QSFP_2_RX3P QSFP_2_RX4N QSFP_2_RX4P QSFP_2_TX1N QSFP_2_TX1P QSFP_2_TX2N QSFP_2_TX2P QSFP_2_TX3N QSFP_2_TX3P QSFP_2_TX4N QSFP_2_TX4P
net class M2_TRANSCEIVER: M2_PER_N0 M2_PER_N1 M2_PER_N2 M2_PER_N3 M2_PER_P0 M2_PER_P1 M2_PER_P2 M2_PER_P3 M2_PET_N0 M2_PET_N0_C M2_PET_N1 M2_PET_N1_C M2_PET_N2 M2_PET_N2_C M2_PET_N3 M2_PET_N3_C M2_PET_P0 M2_PET_P0_C M2_PET_P1 M2_PET_P1_C M2_PET_P2 M2_PET_P2_C M2_PET_P3 M2_PET_P3_C
net class M2_CONTROL: M2_ALERT_B M2_ALERT_B_3V3 M2_CLKREQ_B M2_CLKREQ_B_3V3 M2_DEVSLP M2_DEVSLP_3V3 M2_LED_1_B M2_LED_1_B_3V3 M2_PEDET M2_PEDET_3V3 M2_PERST_B M2_PERST_B_3V3 M2_PEWAKE_B M2_PEWAKE_B_3V3 M2_REFCLK_N M2_REFCLK_P M2_SMB_CLK M2_SMB_CLK_1V8 M2_SMB_DATA M2_SMB_DATA_1V8 M2_SUSCLK M2_SUSCLK_3V3
net class MC2_2MM: MC2A_1 MC2A_2 MC2A_3 MC2A_4 MC2A_5 MC2A_6 MC2A_7 MC2A_8 MC2A_9 MC2A_10 MC2A_11 MC2A_12 MC2A_13 MC2A_14 MC2A_15 MC2A_16 MC2A_17 MC2A_18 MC2A_19 MC2A_20 MC2A_21 MC2A_22 MC2A_23 MC2A_24 MC2A_25 MC2A_26 MC2A_27 MC2A_28 MC2A_29 MC2A_30 MC2A_31 MC2A_32 MC2A_33 MC2A_34 MC2A_35 MC2A_36 MC2A_37 MC2A_39
net class MC1_2MM: MC1A_3 MC1A_4 MC1A_5 MC1A_6 MC1A_7 MC1A_8 MC1A_9 MC1A_10 MC1A_11 MC1A_12 MC1A_13 MC1A_14 MC1A_15 MC1A_16 MC1A_17 MC1A_18 MC1A_19 MC1A_20 MC1A_21 MC1A_22 MC1A_23 MC1A_24 MC1A_25 MC1A_26 MC1A_27 MC1A_28 MC1A_29 MC1A_30 MC1A_31 MC1A_32 MC1A_33 MC1A_34 MC1A_35 MC1A_36 MC1A_37 MC1A_38 MC1A_39 MC1A_40 MC1B_1 MC1B_2 MC1B_3 MC1B_4 MC1B_5 MC1B_6 MC1B_7 MC1B_8 MC1B_9 MC1B_10 MC1B_11 MC1B_12 MC1B_13 MC1B_14 MC1B_15 MC1B_16 MC1B_17 MC1B_18 MC1B_19 MC1B_20 MC1B_21 MC1B_22 MC1B_23 MC1B_24 MC1B_25 MC1B_26 MC1B_27 MC1B_28 MC1B_29 MC1B_30 MC1B_31 MC1B_32 MC1B_33 MC1B_34 MC1B_35 MC1B_36 MC1B_37 MC1B_38 MC1B_39 MC1B_40
net class PORTB: PORTB_C2P_CLKN PORTB_C2P_CLKP PORTB_P2C_CLKN PORTB_P2C_CLKP PORTB_S0_D0P PORTB_S1_D1P PORTB_S2_D0N PORTB_S3_D1N PORTB_S4_D2P PORTB_S5_D3P PORTB_S6_D2N PORTB_S7_D3N PORTB_S8_D4P PORTB_S9_D5P PORTB_S10_D4N PORTB_S11_D5N PORTB_S12_D6P PORTB_S13_D7P PORTB_S14_D6N PORTB_S15_D7N PORTB_S16 PORTB_S17 PORTB_S18 PORTB_S19 PORTB_S20 PORTB_S21 PORTB_S22 PORTB_S23 PORTB_S24 PORTB_S25 PORTB_S26 PORTB_S27
net class PORTA: PORTA_C2P_CLKN PORTA_C2P_CLKP PORTA_P2C_CLKN PORTA_P2C_CLKP PORTA_S0_D0P PORTA_S1_D1P PORTA_S2_D0N PORTA_S3_D1N PORTA_S4_D2P PORTA_S5_D3P PORTA_S6_D2N PORTA_S7_D3N PORTA_S8_D4P PORTA_S9_D5P PORTA_S10_D4N PORTA_S11_D5N PORTA_S12_D6P PORTA_S13_D7P PORTA_S14_D6N PORTA_S15_D7N PORTA_S16 PORTA_S17 PORTA_S18 PORTA_S19 PORTA_S20 PORTA_S21 PORTA_S22 PORTA_S23 PORTA_S24 PORTA_S25 PORTA_S26 PORTA_S27
net class PORTF: PORTF_C2P_CLKN PORTF_C2P_CLKP PORTF_P2C_CLKN PORTF_P2C_CLKP PORTF_REFCLKN PORTF_REFCLKP PORTF_RX0N PORTF_RX0P PORTF_RX1N PORTF_RX1P PORTF_S0 PORTF_S1 PORTF_S2 PORTF_S3 PORTF_S4 PORTF_S5 PORTF_S6 PORTF_S7 PORTF_S8 PORTF_S9 PORTF_TX0N PORTF_TX0P PORTF_TX1N PORTF_TX1P
net class PORTC: PORTC_C2P_CLKN PORTC_C2P_CLKP PORTC_P2C_CLKN PORTC_P2C_CLKP PORTC_S0_D0P PORTC_S1_D1P PORTC_S2_D0N PORTC_S3_D1N PORTC_S4_D2P PORTC_S5_D3P PORTC_S6_D2N PORTC_S7_D3N PORTC_S8_D4P PORTC_S9_D5P PORTC_S10_D4N PORTC_S11_D5N PORTC_S12_D6P PORTC_S13_D7P PORTC_S14_D6N PORTC_S15_D7N PORTC_S16 PORTC_S17 PORTC_S18 PORTC_S19 PORTC_S20 PORTC_S21 PORTC_S22 PORTC_S23 PORTC_S24 PORTC_S25 PORTC_S26 PORTC_S27
net class PORTD: PORTD_C2P_CLKN PORTD_C2P_CLKP PORTD_P2C_CLKN PORTD_P2C_CLKP PORTD_S0_D0P PORTD_S1_D1P PORTD_S3_D1N PORTD_S4_D2P PORTD_S5_D3P PORTD_S6_D2N PORTD_S7_D3N PORTD_S8_D4P PORTD_S9_D5P PORTD_S10_D4N PORTD_S11_D5N PORTD_S12_D6P PORTD_S13_D7P PORTD_S14_D6N PORTD_S15_D7N PORTD_S16 PORTD_S17 PORTD_S18 PORTD_S19 PORTD_S20 PORTD_S21 PORTD_S22 PORTD_S23 PORTD_S24 PORTD_S25 PORTD_S26 PORTD_S27
net class PORTE: PORTE_C2P_CLKN PORTE_C2P_CLKP PORTE_P2C_CLKN PORTE_P2C_CLKP PORTE_REFCLKN PORTE_REFCLKP PORTE_RX0N PORTE_RX0P PORTE_RX1N PORTE_RX1P PORTE_S0 PORTE_S1 PORTE_S2 PORTE_S3 PORTE_S4 PORTE_S5 PORTE_S6 PORTE_S7 PORTE_S8 PORTE_S9 PORTE_TX0N PORTE_TX0P PORTE_TX1N PORTE_TX1P
differential pair class 100ohm_Diff: DP_100MHZ_REFCLK DP_200MHZ_OSC DP_M2_PER_0 DP_M2_PER_1 DP_M2_PER_2 DP_M2_PER_3 DP_M2_PET_0 DP_M2_PET_0_C DP_M2_PET_1 DP_M2_PET_1_C DP_M2_PET_2 DP_M2_PET_2_C DP_M2_PET_3 DP_M2_PET_3_C DP_M2_REFCLK DP_MC1A_3_4 DP_MC1A_5_6 DP_MC1A_7_8 DP_MC1A_9_10 DP_MC1A_11_12 DP_MC1A_13_14 DP_MC1A_15_16 DP_MC1A_17_18 DP_MC1A_19_20 DP_MC1A_21_22 DP_MC1A_23_24 DP_MC1A_25_26 DP_MC1A_27_28 DP_MC1A_29_30 DP_MC1A_31_32 DP_MC1A_33_34 DP_MC1A_35_36 DP_MC1A_37_38 DP_MC1B_1_2 DP_MC1B_3_4 DP_MC1B_5_6 DP_MC1B_7_8 DP_MC1B_9_10 DP_MC1B_11_12 DP_MC1B_13_14 DP_MC1B_15_16 DP_MC1B_17_18 DP_MC1B_19_20 DP_MC1B_21_22 DP_MC1B_23_24 DP_MC1B_25_26 DP_MC1B_27_28 DP_MC1B_29_30 DP_MC1B_31_32 DP_MC1B_33_34 DP_MC1B_35_36 DP_MC1B_37_38 DP_MC1B_39_40 DP_MC2A_1_2 DP_MC2A_3_4 DP_MC2A_5_6 DP_MC2A_7_8 DP_MC2A_9_10 DP_MC2A_11_12 DP_MC2A_13_14 DP_MC2A_15_16 DP_MC2A_17_18 DP_MC2A_19_20 DP_MC2A_21_22 DP_MC2A_23_24 DP_MC2A_25_26 DP_MC2A_27_28 DP_MC2A_29_30 DP_MC2A_31_32 DP_MC2A_33_34 DP_MC2A_35_36 DP_MC2A_37_38 DP_PORTA_C2P_CLK DP_PORTA_D0 DP_PORTA_D1 DP_PORTA_D2 DP_PORTA_D3 DP_PORTA_D4 DP_PORTA_D5 DP_PORTA_D6 DP_PORTA_D7 DP_PORTA_P2C_CLK DP_PORTB_C2P_CLK DP_PORTB_D0 DP_PORTB_D1 DP_PORTB_D2 DP_PORTB_D3 DP_PORTB_D4 DP_PORTB_D5 DP_PORTB_D6 DP_PORTB_D7 DP_PORTB_P2C_CLK DP_PORTC_C2P_CLK DP_PORTC_D0 DP_PORTC_D1 DP_PORTC_D2 DP_PORTC_D3 DP_PORTC_D4 DP_PORTC_D5 DP_PORTC_D6 DP_PORTC_D7 DP_PORTC_P2C_CLK DP_PORTD_C2P_CLK DP_PORTD_D0 DP_PORTD_D1 DP_PORTD_D2 DP_PORTD_D3 DP_PORTD_D4 DP_PORTD_D5 DP_PORTD_D6 DP_PORTD_D7 DP_PORTD_P2C_CLK DP_PORTE_C2P_CLK DP_PORTE_P2C_CLK DP_PORTE_REFCLK DP_PORTE_RX0 DP_PORTE_RX1 DP_PORTE_RX2 DP_PORTE_RX3 DP_PORTE_TX0 DP_PORTE_TX1 DP_PORTE_TX2 DP_PORTE_TX3 DP_PORTF_C2P_CLK DP_PORTF_P2C_CLK DP_PORTF_REFCLK DP_PORTF_RX0 DP_PORTF_RX1 DP_PORTF_RX2 DP_PORTF_RX3 DP_PORTF_TX0 DP_PORTF_TX1 DP_PORTF_TX2 DP_PORTF_TX3 DP_QSFP_1_RX1 DP_QSFP_1_RX2 DP_QSFP_1_RX3 DP_QSFP_1_RX4 DP_QSFP_1_TX1 DP_QSFP_1_TX2 DP_QSFP_1_TX3 DP_QSFP_1_TX4 DP_QSFP_2_RX1 DP_QSFP_2_RX2 DP_QSFP_2_RX3 DP_QSFP_2_RX4 DP_QSFP_2_TX1 DP_QSFP_2_TX2 DP_QSFP_2_TX3 DP_QSFP_2_TX4 DP_RX0 DP_RX1 DP_RX2 DP_RX3 DP_SATA_1_TXA DP_SATA_1_TXA_C DP_SATA_1_TXB DP_SATA_1_TXB_C DP_SATA_2_TXA DP_SATA_2_TXA_C DP_SATA_2_TXB DP_SATA_2_TXB_C DP_SMA_REFCLK DP_SMA_RX0 DP_SMA_RX1 DP_SMA_TX0 DP_TX0 DP_TX1 DP_TX2 DP_TX3 DP_UFL_RX0 DP_UFL_RX1 DP_UFL_TX0 DP_UFL_TX1 DP_XADC_V
differential pair DP_PORTE_TX3: +PORTE_TX3P -PORTE_TX3N
differential pair DP_PORTE_TX2: +PORTE_TX2P -PORTE_TX2N
differential pair DP_PORTE_RX3: +PORTE_RX3P -PORTE_RX3N
differential pair DP_PORTE_RX2: +PORTE_RX2P -PORTE_RX2N
differential pair DP_PORTF_TX3: +PORTF_TX3P -PORTF_TX3N
differential pair DP_PORTF_TX2: +PORTF_TX2P -PORTF_TX2N
differential pair DP_PORTF_RX3: +PORTF_RX3P -PORTF_RX3N
differential pair DP_PORTF_RX2: +PORTF_RX2P -PORTF_RX2N
differential pair DP_MC1A_37_38: +MC1A_37 -MC1A_38
differential pair DP_MC1A_33_34: +MC1A_33 -MC1A_34
differential pair DP_MC1A_29_30: +MC1A_29 -MC1A_30
differential pair DP_MC1A_25_26: +MC1A_25 -MC1A_26
differential pair DP_MC1A_21_22: +MC1A_21 -MC1A_22
differential pair DP_MC1A_17_18: +MC1A_17 -MC1A_18
differential pair DP_MC1A_35_36: +MC1A_35 -MC1A_36
differential pair DP_MC1A_31_32: +MC1A_31 -MC1A_32
differential pair DP_MC1A_27_28: +MC1A_27 -MC1A_28
differential pair DP_MC1A_23_24: +MC1A_23 -MC1A_24
differential pair DP_MC1A_19_20: +MC1A_19 -MC1A_20
differential pair DP_MC1A_15_16: +MC1A_15 -MC1A_16
differential pair DP_MC1A_13_14: +MC1A_13 -MC1A_14
differential pair DP_MC1A_9_10: +MC1A_9 -MC1A_10
differential pair DP_MC1A_11_12: +MC1A_11 -MC1A_12
differential pair DP_MC1A_7_8: +MC1A_7 -MC1A_8
differential pair DP_MC1B_39_40: +MC1B_39 -MC1B_40
differential pair DP_MC1B_35_36: +MC1B_35 -MC1B_36
differential pair DP_MC1B_31_32: +MC1B_31 -MC1B_32
differential pair DP_MC1B_27_28: +MC1B_27 -MC1B_28
differential pair DP_MC1B_37_38: +MC1B_37 -MC1B_38
differential pair DP_MC1B_33_34: +MC1B_33 -MC1B_34
differential pair DP_MC1B_29_30: +MC1B_29 -MC1B_30
differential pair DP_MC1B_23_24: +MC1B_23 -MC1B_24
differential pair DP_MC1B_19_20: +MC1B_19 -MC1B_20
differential pair DP_MC1B_15_16: +MC1B_15 -MC1B_16
differential pair DP_MC1B_11_12: +MC1B_11 -MC1B_12
differential pair DP_MC1B_7_8: +MC1B_7 -MC1B_8
differential pair DP_MC1B_3_4: +MC1B_3 -MC1B_4
differential pair DP_MC1B_25_26: +MC1B_25 -MC1B_26
differential pair DP_MC1B_21_22: +MC1B_21 -MC1B_22
differential pair DP_MC1B_17_18: +MC1B_17 -MC1B_18
differential pair DP_MC1B_13_14: +MC1B_13 -MC1B_14
differential pair DP_MC1B_9_10: +MC1B_9 -MC1B_10
differential pair DP_MC1B_5_6: +MC1B_5 -MC1B_6
differential pair DP_MC1B_1_2: +MC1B_1 -MC1B_2
differential pair DP_MC2A_1_2: +MC2A_1 -MC2A_2
differential pair DP_MC2A_3_4: +MC2A_3 -MC2A_4
differential pair DP_MC2A_7_8: +MC2A_7 -MC2A_8
differential pair DP_MC2A_11_12: +MC2A_11 -MC2A_12
differential pair DP_MC2A_15_16: +MC2A_15 -MC2A_16
differential pair DP_MC2A_5_6: +MC2A_5 -MC2A_6
differential pair DP_MC2A_9_10: +MC2A_9 -MC2A_10
differential pair DP_MC2A_13_14: +MC2A_13 -MC2A_14
differential pair DP_MC2A_17_18: +MC2A_17 -MC2A_18
differential pair DP_MC2A_19_20: +MC2A_19 -MC2A_20
differential pair DP_MC2A_21_22: +MC2A_21 -MC2A_22
differential pair DP_MC2A_23_24: +MC2A_23 -MC2A_24
differential pair DP_MC2A_25_26: +MC2A_25 -MC2A_26
differential pair DP_MC2A_27_28: +MC2A_27 -MC2A_28
differential pair DP_MC2A_29_30: +MC2A_29 -MC2A_30
differential pair DP_MC2A_31_32: +MC2A_31 -MC2A_32
differential pair DP_MC2A_33_34: +MC2A_33 -MC2A_34
differential pair DP_MC2A_35_36: +MC2A_35 -MC2A_36
differential pair DP_MC2A_37_38: +MC2A_37 -MC2A_38
differential pair DP_MC1A_5_6: +MC1A_5 -MC1A_6
differential pair DP_MC1A_3_4: +MC1A_3 -MC1A_4
differential pair DP_TX3: +TXP3 -TXN3
differential pair DP_TX2: +TXP2 -TXN2
differential pair DP_TX1: +TXP1 -TXN1
differential pair DP_TX0: +TXP0 -TXN0
differential pair DP_RX3: +RXP3 -RXN3
differential pair DP_RX2: +RXP2 -RXN2
differential pair DP_RX1: +RXP1 -RXN1
differential pair DP_RX0: +RXP0 -RXN0
differential pair DP_200MHZ_OSC: +100MHZ_OSC_P -100MHZ_OSC_N
differential pair DP_M2_REFCLK: +M2_REFCLK_P -M2_REFCLK_N
differential pair DP_SATA_2_TXB_C: +SATA_2_TXB+_C -SATA_2_TXB-_C
differential pair DP_SATA_2_TXB: +SATA_2_TXB+ -SATA_2_TXB-
differential pair DP_SATA_2_TXA_C: +SATA_2_TXA+_C -SATA_2_TXA-_C
differential pair DP_SATA_2_TXA: +SATA_2_TXA+ -SATA_2_TXA-
differential pair DP_SATA_1_TXB: +SATA_1_TXB+ -SATA_1_TXB-
differential pair DP_SATA_1_TXB_C: +SATA_1_TXB+_C -SATA_1_TXB-_C
differential pair DP_SATA_1_TXA_C: +SATA_1_TXA+_C -SATA_1_TXA-_C
differential pair DP_SATA_1_TXA: +SATA_1_TXA+ -SATA_1_TXA-
differential pair DP_SMA_RX1: +"" -""
differential pair DP_SMA_RX0: +"" -""
differential pair DP_SMA_REFCLK: +SMA_REFCLKP -SMA_REFCLKN
differential pair DP_SMA_TX0: +"" -""
differential pair DP_UFL_TX1: +"" -""
differential pair DP_UFL_TX0: +"" -""
differential pair DP_UFL_RX1: +"" -""
differential pair DP_UFL_RX0: +"" -""
differential pair DP_XADC_V: +XADC_VP -XADC_VN
differential pair DP_QSFP_2_TX4: +QSFP_2_TX4P -QSFP_2_TX4N
differential pair DP_QSFP_2_TX3: +QSFP_2_TX3P -QSFP_2_TX3N
differential pair DP_QSFP_2_TX2: +QSFP_2_TX2P -QSFP_2_TX2N
differential pair DP_QSFP_2_TX1: +QSFP_2_TX1P -QSFP_2_TX1N
differential pair DP_QSFP_2_RX4: +QSFP_2_RX4P -QSFP_2_RX4N
differential pair DP_QSFP_2_RX3: +QSFP_2_RX3P -QSFP_2_RX3N
differential pair DP_QSFP_2_RX2: +QSFP_2_RX2P -QSFP_2_RX2N
differential pair DP_QSFP_2_RX1: +QSFP_2_RX1P -QSFP_2_RX1N
differential pair DP_QSFP_1_TX4: +QSFP_1_TX4P -QSFP_1_TX4N
differential pair DP_QSFP_1_TX3: +QSFP_1_TX3P -QSFP_1_TX3N
differential pair DP_QSFP_1_TX2: +QSFP_1_TX2P -QSFP_1_TX2N
differential pair DP_QSFP_1_TX1: +QSFP_1_TX1P -QSFP_1_TX1N
differential pair DP_QSFP_1_RX4: +QSFP_1_RX4P -QSFP_1_RX4N
differential pair DP_QSFP_1_RX3: +QSFP_1_RX3P -QSFP_1_RX3N
differential pair DP_QSFP_1_RX2: +QSFP_1_RX2P -QSFP_1_RX2N
differential pair DP_QSFP_1_RX1: +QSFP_1_RX1P -QSFP_1_RX1N
differential pair DP_M2_PET_3_C: +M2_PET_P3_C -M2_PET_N3_C
differential pair DP_M2_PET_2_C: +M2_PET_P2_C -M2_PET_N2_C
differential pair DP_M2_PET_1_C: +M2_PET_P1_C -M2_PET_N1_C
differential pair DP_M2_PET_0_C: +M2_PET_P0_C -M2_PET_N0_C
differential pair DP_M2_PET_3: +M2_PET_P3 -M2_PET_N3
differential pair DP_M2_PET_2: +M2_PET_P2 -M2_PET_N2
differential pair DP_M2_PET_1: +M2_PET_P1 -M2_PET_N1
differential pair DP_M2_PET_0: +M2_PET_P0 -M2_PET_N0
differential pair DP_M2_PER_3: +M2_PER_P3 -M2_PER_N3
differential pair DP_M2_PER_2: +M2_PER_P2 -M2_PER_N2
differential pair DP_M2_PER_1: +M2_PER_P1 -M2_PER_N1
differential pair DP_M2_PER_0: +M2_PER_P0 -M2_PER_N0
differential pair DP_PORTF_TX1: +PORTF_TX1P -PORTF_TX1N
differential pair DP_PORTF_TX0: +PORTF_TX0P -PORTF_TX0N
differential pair DP_PORTF_RX1: +PORTF_RX1P -PORTF_RX1N
differential pair DP_PORTF_RX0: +PORTF_RX0P -PORTF_RX0N
differential pair DP_PORTF_REFCLK: +PORTF_REFCLKP -PORTF_REFCLKN
differential pair DP_PORTF_P2C_CLK: +PORTF_P2C_CLKP -PORTF_P2C_CLKN
differential pair DP_PORTF_C2P_CLK: +PORTF_C2P_CLKP -PORTF_C2P_CLKN
differential pair DP_PORTE_TX1: +PORTE_TX1P -PORTE_TX1N
differential pair DP_PORTE_TX0: +PORTE_TX0P -PORTE_TX0N
differential pair DP_PORTE_RX1: +PORTE_RX1P -PORTE_RX1N
differential pair DP_PORTE_RX0: +PORTE_RX0P -PORTE_RX0N
differential pair DP_PORTE_REFCLK: +PORTE_REFCLKP -PORTE_REFCLKN
differential pair DP_PORTE_P2C_CLK: +PORTE_P2C_CLKP -PORTE_P2C_CLKN
differential pair DP_PORTE_C2P_CLK: +PORTE_C2P_CLKP -PORTE_C2P_CLKN
differential pair DP_PORTD_D7: +PORTD_S13_D7P -PORTD_S15_D7N
differential pair DP_PORTD_D6: +PORTD_S12_D6P -PORTD_S14_D6N
differential pair DP_PORTD_D5: +PORTD_S9_D5P -PORTD_S11_D5N
differential pair DP_PORTD_D4: +PORTD_S8_D4P -PORTD_S10_D4N
differential pair DP_PORTD_D3: +PORTD_S5_D3P -PORTD_S7_D3N
differential pair DP_PORTD_D2: +PORTD_S4_D2P -PORTD_S6_D2N
differential pair DP_PORTD_D1: +PORTD_S1_D1P -PORTD_S3_D1N
differential pair DP_PORTD_D0: +PORTD_S0_D0P -PORTD_S2_D0N
differential pair DP_PORTD_P2C_CLK: +PORTD_P2C_CLKP -PORTD_P2C_CLKN
differential pair DP_PORTD_C2P_CLK: +PORTD_C2P_CLKP -PORTD_C2P_CLKN
differential pair DP_PORTC_D7: +PORTC_S13_D7P -PORTC_S15_D7N
differential pair DP_PORTC_D6: +PORTC_S12_D6P -PORTC_S14_D6N
differential pair DP_PORTC_D5: +PORTC_S9_D5P -PORTC_S11_D5N
differential pair DP_PORTC_D4: +PORTC_S8_D4P -PORTC_S10_D4N
differential pair DP_PORTC_D3: +PORTC_S5_D3P -PORTC_S7_D3N
differential pair DP_PORTC_D2: +PORTC_S4_D2P -PORTC_S6_D2N
differential pair DP_PORTC_D1: +PORTC_S1_D1P -PORTC_S3_D1N
differential pair DP_PORTC_D0: +PORTC_S0_D0P -PORTC_S2_D0N
differential pair DP_PORTC_P2C_CLK: +PORTC_P2C_CLKP -PORTC_P2C_CLKN
differential pair DP_PORTC_C2P_CLK: +PORTC_C2P_CLKP -PORTC_C2P_CLKN
differential pair DP_PORTB_D7: +PORTB_S13_D7P -PORTB_S15_D7N
differential pair DP_PORTB_D6: +PORTB_S12_D6P -PORTB_S14_D6N
differential pair DP_PORTB_D5: +PORTB_S9_D5P -PORTB_S11_D5N
differential pair DP_PORTB_D4: +PORTB_S8_D4P -PORTB_S10_D4N
differential pair DP_PORTB_D3: +PORTB_S5_D3P -PORTB_S7_D3N
differential pair DP_PORTB_D2: +PORTB_S4_D2P -PORTB_S6_D2N
differential pair DP_PORTB_D1: +PORTB_S1_D1P -PORTB_S3_D1N
differential pair DP_PORTB_D0: +PORTB_S0_D0P -PORTB_S2_D0N
differential pair DP_PORTB_P2C_CLK: +PORTB_P2C_CLKP -PORTB_P2C_CLKN
differential pair DP_PORTB_C2P_CLK: +PORTB_C2P_CLKP -PORTB_C2P_CLKN
differential pair DP_PORTA_D7: +PORTA_S13_D7P -PORTA_S15_D7N
differential pair DP_PORTA_D6: +PORTA_S12_D6P -PORTA_S14_D6N
differential pair DP_PORTA_D5: +PORTA_S9_D5P -PORTA_S11_D5N
differential pair DP_PORTA_D4: +PORTA_S8_D4P -PORTA_S10_D4N
differential pair DP_PORTA_D3: +PORTA_S5_D3P -PORTA_S7_D3N
differential pair DP_PORTA_D2: +PORTA_S4_D2P -PORTA_S6_D2N
differential pair DP_PORTA_D1: +PORTA_S1_D1P -PORTA_S3_D1N
differential pair DP_PORTA_D0: +PORTA_S0_D0P -PORTA_S2_D0N
differential pair DP_PORTA_P2C_CLK: +PORTA_P2C_CLKP -PORTA_P2C_CLKN
differential pair DP_PORTA_C2P_CLK: +PORTA_C2P_CLKP -PORTA_C2P_CLKN
differential pair DP_100MHZ_REFCLK: +"100MHZ _REFCLK_P" -100MHZ_REFCLK_N

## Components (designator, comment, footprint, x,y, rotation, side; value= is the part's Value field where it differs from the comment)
*1 "Opal Kelly Logo" okLogo-23x5 13.785,-50.108 r0 top
C1 "SM-0402, 10%, 10v" CAPC1005X06A 22.7,65.818 r90 top value="0.1 u"
C2 "SM-0402, 10%, 10v" CAPC1005X06A 46.144,36.277 r270 top value="0.1 u"
C4 "SM-0402, 10%, 10v" CAPC1005X06A 147.252,18.644 r180 top value="0.1 u"
C6 "SM-0402, 10%, 10v" CAPC1005X06A 210.99,33.61 r270 top value="0.1 u"
C7 "SM-0402, 10%, 10v" CAPC1005X06A 210.99,16.567 r270 top value="0.1 u"
C8 "SM-0402, 10%, 10v" CAPC1005X06A 210,33.61 r270 top value="0.1 u"
C9 "SM-0402, 10%, 10v" CAPC1005X06A 210,16.567 r270 top value="0.1 u"
C10 "SM-0402, 10%, 10v" CAPC1005X06A 211.016,67.545 r270 top value="0.1 u"
C11 "SM-0402, 10%, 10v" CAPC1005X06A 210.99,50.517 r270 top value="0.1 u"
C12 "SM-0402, 10%, 10v" CAPC1005X06A 210,67.545 r270 top value="0.1 u"
C13 "SM-0402, 10%, 10v" CAPC1005X06A 210,50.517 r270 top value="0.1 u"
C14 "SM-0402, 10%, 10v" CAPC1005X06A 234.033,19.449 r180 top value="0.1 u"
C15 "SM-0402, 10%, 10v" CAPC1005X06A 234.033,1.475 r180 top value="0.1 u"
C16 "SM-0402, 10%, 10v" CAPC1005X06A 234.033,18.449 r180 top value="0.1 u"
C17 "SM-0402, 10%, 10v" CAPC1005X06A 234.033,0.475 r180 top value="0.1 u"
C18 "SM-0402, 10%, 10v" CAPC1005X06A 234.033,55.475 r180 top value="0.1 u"
C19 "SM-0402, 10%, 10v" CAPC1005X06A 234.033,37.449 r180 top value="0.1 u"
C20 "SM-0402, 10%, 10v" CAPC1005X06A 234.033,54.475 r180 top value="0.1 u"
C21 "SM-0402, 10%, 10v" CAPC1005X06A 234.033,36.449 r180 top value="0.1 u"
C22 "SM-0402, 10%, 10v" CAPC1005X06A 157.498,65.818 r270 top value="0.1 u"
C23 "SM-0402, 10%, 10v" CAPC1005X06A 177.488,65.818 r270 top value="0.1 u"
C24 "SM-0402, 10%, 10v" CAPC1005X06A 158.395,65.818 r270 top value="0.1 u"
C25 "SM-0402, 10%, 10v" CAPC1005X06A 178.402,65.818 r270 top value="0.1 u"
C26 "SM-0402, 10%, 10v" CAPC1005X06A 161.308,65.818 r270 top value="0.1 u"
C27 "SM-0402, 10%, 10v" CAPC1005X06A 181.298,65.818 r270 top value="0.1 u"
C28 "SM-0402, 10%, 10v" CAPC1005X06A 162.222,65.818 r270 top value="0.1 u"
C29 "SM-0402, 10%, 10v" CAPC1005X06A 182.237,65.818 r270 top value="0.1 u"
C30 "LMK107BJ106MALTD" CAPC1608N 60.308,58.058 r270 top value=10u
C31 "JMK105BBJ475MV-F" CAPC1005X06A 59.038,57.524 r270 top value=4.7u
C32 "C1005X5R1A335K050BC" CAPC1005X06A 58.022,58.134 r270 top value=3.3u
C33 "C3216X5R1V226M160AC" CAPC3216N 56.38,60.077 r90 top value="22 u"
C34 "TMK105BJ104KV-F" CAPC1005X06A 56.457,56.966 r180 top value="0.1 u"
C35 "C0402C104K8PACTU" CAPC1005X06A 65.331,48.382 r90 top value="0.1 u"
C36 "EEE-FK1E221P" CAPAE9083X70N 30.472,52.432 r270 top value=220u
C37 "TMK105BJ104KV-F" CAPC1005X06A 23.665,52.508 r90 top value="0.1 u"
C38 "C0402C104K8PACTU" CAPC1005X06A 74.343,50.793 r270 top value="0.1 u"
C39 "LMK316AB7226KL-TR" CAPC3216N 76.044,50.108 r270 top value=22u
C40 "LMK316AB7226KL-TR" CAPC3216N 78.351,50.108 r270 top value=22u
C41 "SM-0402, 5%, 50v" CAPC1005X06A 63.883,47.221 r270 top value="56 p"
C42 "C0402C472K5RACTU" CAPC1005X06A 60.41,45.459 r180 top value="4.7 n"
C43 "C0402C104K8PACTU" CAPC1005X06A 59.93,46.806 r270 top value="0.1 u"
C44 "C0402C220J5GACTU" CAPC1005X06A 62.366,45.459 r0 top value="22 p"
C45 "C0402C104K8PACTU" CAPC1005X06A 65.642,55.797 r270 top value="0.1 u"
C46 "C3216X5R1V226M160AC" CAPC3216N 65.49,52.14 r90 top value="22 u"
C47 "TMK105BJ104KV-F" CAPC1005X06A 63.807,52.142 r90 top value="0.1 u"
C48 "C0402C104K8PACTU" CAPC1005X06A 74.343,54.146 r90 top value="0.1 u"
C49 "LMK316AB7226KL-TR" CAPC3216N 76.052,54.817 r90 top value=22u
C50 "LMK316AB7226KL-TR" CAPC3216N 78.351,54.817 r90 top value=22u
C51 "C0402C104K8PACTU" CAPC1005X06A 61.578,57.499 r270 top value="0.1 u"
C52 "SM-0402, 5%, 50v" CAPC1005X06A 65.642,57.702 r90 top value="56 p"
C53 "C0402C472K5RACTU" CAPC1005X06A 61.592,59.404 r90 top value="4.7 n"
C54 "C0402C220J5GACTU" CAPC1005X06A 62.594,59.404 r90 top value="22 p"
C55 "C0402C104K8PACTU" CAPC1005X06A 54.729,60.511 r90 top value="0.1 u"
C56 "C0402C104K8PACTU" CAPC1005X06A 52.053,54.807 r270 top value="0.1 u"
C57 "C3216X5R1V226M160AC" CAPC3216N 51.975,51.682 r180 top value="22 u"
C58 "TMK105BJ104KV-F" CAPC1005X06A 53.314,53.335 r180 top value="0.1 u"
C59 "C0402C104K8PACTU" CAPC1005X06A 42.339,54.2 r90 top value="0.1 u"
C60 "LMK316AB7226KL-TR" CAPC3216N 40.662,54.835 r90 top value=22u
C61 "LMK316AB7226KL-TR" CAPC3216N 38.372,54.835 r90 top value=22u
C62 "C0402C560J5GACTU" CAPC1005X06A 52.892,56.712 r90 top value="56 p"
C63 "C0402C104K8PACTU" CAPC1005X06A 56.067,47.225 r270 top value="0.1 u"
C64 "C0402C472K5RACTU" CAPC1005X06A 53.73,58.591 r90 top value="4.7 n"
C65 "C0402C220J5GACTU" CAPC1005X06A 54.746,58.566 r90 top value="22 p"
C66 "C0402C104K8PACTU" CAPC1005X06A 52.053,49.574 r90 top value="0.1 u"
C67 "C0402C104K8PACTU" CAPC1005X06A 42.339,50.768 r270 top value="0.1 u"
C68 "LMK316AB7226KL-TR" CAPC3216N 40.662,50.108 r270 top value=22u
C69 "LMK316AB7226KL-TR" CAPC3216N 38.372,50.108 r270 top value=22u
C70 "C0402C560J5GACTU" CAPC1005X06A 53.069,47.727 r270 top value="56 p"
C71 "SM-0402, 5%, 50V, NP0" CAPC1005X06A 57.972,45.345 r90 top value="100 p"
C72 "C0402C472K5RACTU" CAPC1005X06A 55.051,45.434 r270 top value="4.7 n"
C73 "GJM1555C1H5R0CB01D" CAPC1005X06A 58.937,45.929 r90 top value="5 p"
C74 "C0402C220J5GACTU" CAPC1005X06A 54.035,45.431 r270 top value="22 p"
C75 "SM-0402, 10%, 10v" CAPC1005X06A 150.543,32.403 r0 top value="0.1 u"
C76 "SM-0402, 10%, 10v" CAPC1005X06A 152.549,33.394 r270 top value="0.1 u"
C77 "SM-0402, 10%, 10V, X5R" CAPC1005X06A 160.658,42.876 r270 top value="0.22 u"
C78 "SM-0402, 10%, 10V, X5R" CAPC1005X06A 161.658,42.876 r270 top value="0.22 u"
C79 "SM-0402, 10%, 10V, X5R" CAPC1005X06A 163.67,42.876 r270 top value="0.22 u"
C80 "SM-0402, 10%, 10V, X5R" CAPC1005X06A 164.661,42.876 r270 top value="0.22 u"
C81 "SM-0402, 10%, 10V, X5R" CAPC1005X06A 166.658,42.876 r270 top value="0.22 u"
C82 "SM-0402, 10%, 10V, X5R" CAPC1005X06A 167.658,42.876 r270 top value="0.22 u"
C83 "SM-0402, 10%, 10V, X5R" CAPC1005X06A 169.664,42.876 r270 top value="0.22 u"
C84 "SM-0402, 10%, 10V, X5R" CAPC1005X06A 170.658,42.876 r270 top value="0.22 u"
C85 "SM-0402, 10%, 10v" CAPC1005X06A 146.152,12.047 r0 top value="0.1 u"
C86 "SM-0402, 10%, 10v" CAPC1005X06A 151.079,11.92 r90 top value="0.1 u"
C88 "SM-0402, 10%, 10v" CAPC1005X06A 184.508,42.564 r90 top value="0.1 u"
C90 "SM-0402, 10%, 10v" CAPC1005X06A 185.641,-43.601 r90 top value="0.1 u"
C91 "SM-1206, 10%, 10v, X7R" CAPC3216N 187.317,-44.312 r90 top value=22u
C92 "SM-0402, 10%, 10v" CAPC1005X06A 185.641,-53.211 r90 top value="0.1 u"
C93 "SM-1206, 10%, 10v, X7R" CAPC3216N 187.317,-53.872 r90 top value=22u
C94 "SM-1206, 10%, 10v, X7R" CAPC3216N 187.317,-49.088 r90 top value=22u
C95 "SM-0402, 10%, 10v" CAPC1005X06A 185.641,-48.41 r90 top value="0.1 u"
C96 "SM-0402, 10%, 10v" CAPC1005X06A 174.351,-48.86 r0 top value="0.1 u"
C97 "SM-0402, 10%, 10v" CAPC1005X06A 179.289,-49.032 r90 top value="0.1 u"
C98 "SM-0402, 10%, 10v" CAPC1005X06A 182.472,-37.814 r0 top value="0.1 u"
C99 "SM-0402, 10%, 10v" CAPC1005X06A 184.453,-36.548 r270 top value="0.1 u"
C100 "SM-0402, 10%, 10v" CAPC1005X06A 176.421,-53.594 r270 top value="0.1 u"
C101 "SM-0402, 10%, 10v" CAPC1005X06A 177.449,-53.594 r270 top value="0.1 u"
C102 "SM-0402, 10%, 10v" CAPC1005X06A 185.616,-17.566 r90 top value="0.1 u"
C103 "SM-1206, 10%, 10v, X7R" CAPC3216N 187.292,-18.201 r90 top value=22u
C104 "SM-0402, 10%, 10v" CAPC1005X06A 185.641,-27.045 r90 top value="0.1 u"
C105 "SM-1206, 10%, 10v, X7R" CAPC3216N 187.292,-27.705 r90 top value=22u
C106 "SM-1206, 10%, 10v, X7R" CAPC3216N 187.292,-22.951 r90 top value=22u
C107 "SM-0402, 10%, 10v" CAPC1005X06A 185.59,-22.291 r90 top value="0.1 u"
C108 "SM-0402, 10%, 10v" CAPC1005X06A 183.025,-31.213 r270 top value="0.1 u"
C109 "SM-0402, 10%, 10v" CAPC1005X06A 184.041,-31.213 r270 top value="0.1 u"
D1 "POWER" CD1608-0603-PIN1-CATHODE 12.795,64.37 r90 top
FB1 "220 OHM 2000MA 0805" RESC2012N 183.38,-42.766 r0 top value=220
FB2 "220 OHM 2000MA 0805" RESC2012N 183.38,-52.373 r0 top value=220
FB3 "220 OHM 2000MA 0805" RESC2012N 183.38,-47.564 r180 top value=220
FB4 "220 OHM 2000MA 0805" RESC2012N 183.355,-16.728 r0 top value=220
FB5 "220 OHM 2000MA 0805" RESC2012N 183.406,-26.207 r0 top value=220
FB6 "220 OHM 2000MA 0805" RESC2012N 183.33,-21.452 r180 top value=220
FB7 "220 OHM 2000MA 0805" RESC2012N 147.693,17.151 r180 top value=220
FID1 "FIDUCIAL" FID1MM/2MM-SS 21.582,72.091 r90 top
FID2 "FIDUCIAL" FID1MM/2MM-SS 227.272,71.228 r90 top
FID3 "FIDUCIAL" FID1MM/2MM-SS 227.449,-70.199 r90 top
FID4 "FIDUCIAL" FID1MM/2MM-SS 14.47,-62.884 r90 top
FID5 "FIDUCIAL" FID1MM/2MM-SS 17.874,35.998 r90 top
FID6 "FIDUCIAL" FID1MM/2MM-SS 136.619,40.113 r90 top
FID7 "FIDUCIAL" FID1MM/2MM-SS 136.55,-52.654 r90 top
FID8 "FIDUCIAL" FID1MM/2MM-SS 20.541,-39.262 r90 top
J1 "QSE-020-01-F-D-A" QSE-020-01-X-D-A-L 70,70 r180 top locked
J2 "QSE-020-01-F-D-A" QSE-020-01-X-D-A-L 117,70 r180 top locked
J3 "87831-1420" XILINX-JTAG 33,65 r0 top
J4 "QSE-020-01-F-D-A" QSE-020-01-X-D-A-L 47,-70 r0 top locked
J5 "QSE-020-01-F-D-A" QSE-020-01-X-D-A-L 94,-70 r0 top locked
J6 "RXP2" SMA 219,34.026 r180 top
J7 "TXP2" SMA 219,17.026 r180 top
J8 "QSH-020-01-F-D-DP-A" QSH-020-01-X-D-DP-A-L 148,-70 r0 top locked
J9 "RXN2" SMA 202,34.026 r180 top
J10 "TXN2" SMA 202,17.026 r180 top
J11 "RXP3" SMA 219,68 r180 top
J12 "TXP3" SMA 219,51 r180 top
J13 "RXN3" SMA 202,68 r180 top
J14 "TXN3" SMA 202,51 r180 top
J15 "RXP0" UFL-R-SMT-1 234.5,23 r0 top
J16 "TXP0" UFL-R-SMT-1 234.5,5 r0 top
J17 "RXN0" UFL-R-SMT-1 234.5,15 r180 top
J18 "TXN0" UFL-R-SMT-1 234.5,-3 r180 top
J19 "RXP1" UFL-R-SMT-1 234.5,59 r0 top
J20 "TXP1" UFL-R-SMT-1 234.5,41 r0 top
J21 "RXN1" UFL-R-SMT-1 234.5,51 r180 top
J22 "TXN1" UFL-R-SMT-1 234.5,33 r180 top
J23 "QSH-020-01-F-D-DP-A" QSH-020-01-X-D-DP-A-L 200,-70 r0 top locked
J24 "REFCLKP" SMA 219,0 r180 top
J25 "REFCLKN" SMA 201.994,-0.029 r180 top
J26 "67800-5005" MOLEX-67800-5005 160,70 r180 top locked
J27 "67800-5005" MOLEX-67800-5005 180,70 r180 top locked
J28 "PJ-102AH" CUI-PJ102A -2.2,52.965 r270 top
J30 "FS1-Z38-20Z6-60" QSFP28_RECEPTACLE_SFF-8679 203,-56 r90 top locked
J31 "FS1-Z38-20Z6-60" QSFP28_RECEPTACLE_SFF-8679 203,-30 r90 top locked
J32 "MDT420M01001" M2-CONNECTOR_M-KEYING 167.658,35.586 r0 top locked
JSO1 "Jack Screw Standoff" JSO-0515-01 65,36.5 r0 top locked
JSO2 "Jack Screw Standoff" JSO-0515-01 139,36.5 r0 top locked
JSO3 "Jack Screw Standoff" JSO-0515-01 65,-36.5 r0 top locked
JSO4 "Jack Screw Standoff" JSO-0515-01 139,-36.5 r0 top locked
L1 "XAL6030-222MEB" XAL60XX 70.436,48.482 r0 top value=2.2u
L2 "XAL6030-222MEB" XAL60XX 70.436,56.483 r0 top value=2.2u
L3 "XAL6030-222MEB" XAL60XX 46.225,56.534 r180 top value=2.2u
L4 "XAL6030-222MEB" XAL60XX 46.225,48.431 r180 top value=2.2u
MC1 "QTH-090-01-F-D-A" QTH-090-01-X-D 102,36.5 r0 top locked
MC1A "0877584016" HDR2X20-2MM 111,54 r0 top
MC1B "0877584016" HDR2X20-2MM 157,54 r0 top
MC1C "Header, 20-Pin, Single Row" HDR1X20-2MM 111,51 r0 top
MC1D "Header, 20-Pin, Single Row" HDR1X20-2MM 157,51 r0 top
MC2 "QTH-090-01-F-D-A" QTH-090-01-X-D 102,-36.5 r0 top locked
MC2A "0877584016" HDR2X20-2MM 113,-53.5 r0 top
MC2B "Header, 20-Pin, Single Row" HDR1X20-2MM 113,-50.5 r0 top
MC3 "QTH-060-01-L-D-DP-A" QTH-060-01-X-D-DP-A 139,0 r270 top locked
MH1 "MTG" MTG-3.2/6.5-PTH 4,38.5 r0 top
MH2 "MTG" MTG-3.2/6.5-PTH 4,-38.5 r0 top
MH5 "MTG" MTG-3.2/6.5-PTH 5,70 r0 top locked
MH6 "MTG" MTG-3.2/6.5-PTH 235,70 r0 top locked
MH7 "MTG" MTG-3.2/6.5-PTH 235,-70 r0 top locked
MH8 "MTG" MTG-3.2/6.5-PTH 5,-70 r0 top locked
MH9 "MTG" MTG-3.2/6.5-PTH 53,70 r180 top locked
MH10 "MTG" MTG-3.2/6.5-PTH 87,70 r180 top locked
MH11 "MTG" MTG-3.2/6.5-PTH 100,70 r180 top locked
MH12 "MTG" MTG-3.2/6.5-PTH 134,70 r180 top locked
MH13 "MTG" MTG-3.2/6.5-PTH 30,-70 r0 top locked
MH14 "MTG" MTG-3.2/6.5-PTH 64,-70 r0 top locked
MH15 "MTG" MTG-3.2/6.5-PTH 77,-70 r0 top locked
MH16 "MTG" MTG-3.2/6.5-PTH 111,-70 r0 top locked
MH17 "MTG" MTG-3.2/6.5-PTH 129.09,-70 r270 top
MH18 "MTG" MTG-3.2/6.5-PTH 166.91,-70 r270 top
MH19 "MTG" MTG-3.2/6.5-PTH 181.09,-70 r270 top
MH20 "MTG" MTG-3.2/6.5-PTH 218.91,-70 r270 top
Q1 "2.2A, 30V" SOT23-95P240X110 15.586,63.347 r90 top
QSFP1 "Pressfit" QSFP28_SINGLE_CAGE 203,-56 r90 top locked
QSFP2 "Pressfit" QSFP28_SINGLE_CAGE 203,-30 r90 top locked
R1 "CRCW0402210KFKED" RESC1005X06A 77.259,64.04 r180 top value="210 k"
R2 "CRCW040284K5FKED" RESC1005X06A 124.275,64.04 r180 top value="84.5 k"
R3 "SM-0402, 1%, 1/16W" RESC1005X06A 56.119,34.118 r0 top value="10.0 k"
R4 "SM-0402, 1%, 1/16W" RESC1005X06A 56.119,36.1 r0 top value="10.0 k"
R5 "SM-0402, 1%, 1/16W" RESC1005X06A 56.119,38.081 r0 top value="10.0 k"
R6 "SM-0402, 1%, 1/16W" RESC1005X06A 56.119,35.109 r180 top value="10.0 k"
R7 "SM-0402, 1%, 1/16W" RESC1005X06A 56.119,37.09 r180 top value="10.0 k"
R8 "SM-0402, 1%, 1/16W" RESC1005X06A 56.119,39.071 r180 top value="10.0 k"
R9 "RC0402FR-078K87L" RESC1005X06A 39.743,-63.926 r0 top value="8.87 k"
R10 "RC0402FR-076K98L" RESC1005X06A 86.752,-64.154 r0 top value="6.98 k"
R11 "SM-0402, 1%, 1/16W" RESC1005X06A 145.636,20.987 r90 top value=100
R12 "RC0402FR-075K36L" RESC1005X06A 140.81,-64.154 r0 top value="5.36 k"
R13 "CRCW04024K02FKED" RESC1005X06A 192.75,-64.23 r0 top value="4.02 k"
R14 "CRCW040210K0FKED" RESC1005X06A 56.067,45.371 r270 top value="10.0 k"
R15 "CRCW040210K0FKED" RESC1005X06A 59.022,59.442 r90 top value="10.0 k"
R16 "SM-0402, 1%, 1/16W" RESC1005X06A 62.918,47.221 r270 top value="31.6 k"
R17 "SM-0402, 1%, 1/16W" RESC1005X06A 62.003,47.221 r90 top value="10.0 k"
R18 "CRCW040215K0FKED" RESC1005X06A 60.893,46.856 r270 top value="15 k"
R19 "SM-0402, 1%, 1/16W" RESC1005X06A 64.677,57.702 r90 top value="31.6 k"
R20 "SM-0402, 1%, 1/16W" RESC1005X06A 63.763,57.702 r270 top value="10.0 k"
R21 "CRCW040215K0FKED" RESC1005X06A 62.557,57.499 r90 top value="15 k"
R22 "SM-0402, 1%, 1/16W" RESC1005X06A 51.926,56.712 r90 top value="31.6 k"
R23 "CRCW040215K0FKED" RESC1005X06A 54.771,56.712 r90 top value="15 k"
R24 "SM-0402, 1%, 1/16W" RESC1005X06A 53.857,56.712 r270 top value="10.0 k"
R25 "CRCW040239K2FKED" RESC1005X06A 57.027,45.371 r90 top value="39.2 k"
R26 "SM-0402, 1%, 1/16W" RESC1005X06A 52.104,47.727 r270 top value="52.3 k"
R27 "CRCW040215K0FKED" RESC1005X06A 55.101,47.288 r270 top value="15 k"
R28 "CRCW0402374KFKED" RESC1005X06A 57.99,47.214 r90 top value="374 k"
R29 "SM-0402, 1%, 1/16W" RESC1005X06A 54.035,47.72 r90 top value="10.0 k"
R30 "CRCW04022K00FKED" RESC1005X06A 14.827,65.665 r0 top value="2.0 k"
R31 "CRCW040210K0FKED" RESC1005X06A 17.85,62.846 r90 top value="10.0 k"
R32 "SM-0402, 1%, 1/16W" RESC1005X06A 153.358,13.837 r0 top value=49.9k
R33 "SM-0402, 1%, 1/16W" RESC1005X06A 150.543,31.438 r180 top value="3.01 k"
R34 "SM-0402, 1%, 1/16W" RESC1005X06A 150.538,30.385 r180 top value="3.01 k"
R35 "SM-0402, 1%, 1/16W" RESC1005X06A 154.531,32.098 r0 top value="3.01 k"
R36 "SM-0402, 1%, 1/16W" RESC1005X06A 154.526,31.02 r0 top value="3.01 k"
R37 "SM-0402, 1%, 1/16W" RESC1005X06A 153.358,12.637 r0 top value=49.9k
R38 "SM-0402, 1%, 1/16W" RESC1005X06A 153.358,11.436 r0 top value=49.9k
R39 "SM-0402, 1%, 1/16W" RESC1005X06A 153.358,10.237 r0 top value=49.9k
R40 "SM-0402, 1%, 1/16W" RESC1005X06A 179.149,45.434 r0 top value=0
R41 "SM-0402, 1%, 1/16W" RESC1005X06A 153.358,9.037 r0 top value=49.9k
R45 "SM-0402, 1%, 1/16W" RESC1005X06A 182.479,-38.78 r180 top value="3.01 k"
R46 "SM-0402, 1%, 1/16W" RESC1005X06A 182.479,-39.694 r180 top value="3.01 k"
R47 "SM-0402, 1%, 1/16W" RESC1005X06A 186.358,-37.84 r0 top value="3.01 k"
R48 "SM-0402, 1%, 1/16W" RESC1005X06A 186.358,-38.754 r0 top value="3.01 k"
R49 "SM-0402, 1%, 1/16W" RESC1005X06A 175.47,-55.626 r180 top value="3.01 k"
R50 "SM-0402, 1%, 1/16W" RESC1005X06A 175.47,-56.744 r180 top value="3.01 k"
R51 "SM-0402, 1%, 1/16W" RESC1005X06A 179.379,-54.915 r0 top value="3.01 k"
R52 "SM-0402, 1%, 1/16W" RESC1005X06A 179.379,-55.829 r0 top value="3.01 k"
R57 "SM-0402, 1%, 1/16W" RESC1005X06A 182.034,-33.22 r180 top value="3.01 k"
R58 "SM-0402, 1%, 1/16W" RESC1005X06A 182.034,-34.337 r180 top value="3.01 k"
R59 "SM-0402, 1%, 1/16W" RESC1005X06A 177.803,45.891 r270 top value=49.9
R60 "SM-0402, 1%, 1/16W" RESC1005X06A 177.803,44.063 r90 top value=49.9
R61 "SM-0402, 1%, 1/16W" RESC1005X06A 179.149,44.52 r0 top value=0
R62 "SM-0402, 1%, 1/16W" RESC1005X06A 185.971,-32.519 r0 top value="3.01 k"
R63 "SM-0402, 1%, 1/16W" RESC1005X06A 185.971,-33.423 r0 top value="3.01 k"
SO1 "Standoff" 9774025151R-NO-PASTE 167.658,7.336 r0 top
SO2 "Standoff" 9774025151R-NO-PASTE 167.658,-4.664 r0 top
SO3 "Standoff" 9774025151R-NO-PASTE 167.658,-22.664 r0 top
SO4 "Standoff" 9774025151R-NO-PASTE 167.658,-42.664 r0 top
TP1 "VIO1" TP-PTH-65/100#1 128,59.5 r0 top
TP2 "+VDCIN" TP-PTH-65/100#1 41.75,72.828 r0 top
TP3 "VIO2" TP-PTH-65/100#2 69.997,-53.012 r0 top
TP4 "+3.3VDD" TP-PTH-65/100#1 115.802,59.5 r0 top
TP6 "VREF1" TP-PTH-65/100#1 155,59.5 r0 top
TP7 "+1.8VDD" TP-PTH-65/100#1 141,59.5 r0 top
TP9 "VREF2" TP-PTH-65/100#1 62,-53 r90 top
TP10 "DGND" TP-PTH-65/100#1 157.447,-52.6 r90 top
TP12 "VCCBATT" TP-PTH-65/100#1 77.997,-53 r90 top
TP13 "DGND" TP-PTH-65/100#3 188.511,59.125 r90 top
TP15 "DGND" TP-PTH-65/100#1 85.997,-53 r90 top
TP17 "+3.3V_QSFP" TP-SMD40 80.523,48.673 r270 top
TP18 "+3.3V_M.2" TP-SMD40 80.498,56.252 r90 top
TP19 "+3.3V_SZG" TP-SMD40 38.372,58.68 r180 top
TP20 "+5V_SZG" TP-SMD40 38.346,46.26 r90 top
TP21 "TESTPOINT-SMD40" TP-SMD40 59.352,43.974 r90 top
U1 "24FC256-I/SN" SO-G8 50.589,37.725 r90 top
U2 "ASDMPLV-100.000MHZ-LR-T" OSC_SMD_25x20 147.554,20.669 r90 top
U3 "TPS65400RGZT" PVQFN-48 59.292,52.14 r180 top locked
U4 "FXMAR2102L8X" FXMAR2102L8X 152.549,31.387 r0 top
U5 "TXB0108DQSR" TXB0108DQSR 148.898,11.869 r270 top
U6 "ASFLMPHC-100.000MHZ-LR-T" OSC_SMD_5X32 182.067,44.309 r90 top
U7 "TXB0108DQSR" TXB0108DQSR 177.108,-49.051 r270 top
U8 "FXMAR2102L8X" FXMAR2102L8X 184.447,-38.551 r0 top
U9 "FXMAR2102L8X" FXMAR2102L8X 177.441,-55.62 r0 top
U10 "FXMAR2102L8X" FXMAR2102L8X 184.041,-33.217 r0 top

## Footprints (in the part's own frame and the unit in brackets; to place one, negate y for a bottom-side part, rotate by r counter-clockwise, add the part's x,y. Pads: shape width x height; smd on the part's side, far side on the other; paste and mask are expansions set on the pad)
9774025151R-NO-PASTE [mm]
  round 6 hole 3.7: 1(0,0)
CAPAE9083X70N [mm] "Aluminum Electrolytic Capacitor, Body 8.30x8.30x7.00mm, IPC Medium Density"
  rect 3.6x1.65 smd: 1(-3.325,0) 2(3.325,0)
  silkscreen extent -4.25,-4.25 4.25,4.25
CAPC1005X06A [mm] "Chip Capacitor, 2-Leads, Body 1.00x0.50mm, OK custom footprint"
  rect 0.52x0.55 smd mask+0.051: 1(-0.51,0) 2(0.51,0)
CAPC1608N [mm] "Chip Capacitor, Body 1.6x0.8mm, IPC Medium Density"
  rect 1x1 smd: 1(-0.8,0) 2(0.8,0)
  silkscreen extent -0.8,-0.68 0.8,0.68, body extent -0.87,-0.48 0.87,0.48, height 0.85
CAPC3216N [mm] "Chip Capacitor, Body 3.2x1.6mm, IPC Medium Density"
  rect 1.3x1.8 smd: 1(-1.45,0) 2(1.45,0)
  silkscreen extent -1.2,-1.08 1.2,1.08, body extent -1.7,-0.9 1.7,0.9, height 1.35
CD1608-0603-PIN1-CATHODE [mm] "Chip Diode; Body 1.6 x 0.8 mm (LxW typ)"
  rect 1.1x1 smd: 1(-0.85,0) 2(0.85,0)
  silkscreen extent -1.58,-0.68 0.6,0.68
CUI-PJ102A [mm] "2.1mm/5.5mm DC power jack"
  round 2.25 hole 1.5: 1(0,13.7) 2(0,7.7) 3(4.7,10.7)
  silkscreen extent -4.5,0 4.5,14.5
FID1MM/2MM-SS [mm] "Fiducial 1mm copper, 2mm soldermask, single-side"
  round 1 smd paste-0.5 mask+0.5: FID?(0,0)
FXMAR2102L8X [mm]
  rect 0.4x0.25 smd mask+0.051: 1(-0.605,0.5) 2(-0.605,0) 3(-0.605,-0.5) 5(0.605,-0.5) 6(0.605,0) 7(0.605,0.5)
  rect 0.25x0.45 smd mask+0.051: 4(0,-0.575) 8(0,0.575)
HDR1X20-2MM [mm] "2mm 1x20 Header"
  rect 1.3x1.3 hole 0.8: 1(-19,0)
  round 1.3 hole 0.8: 2(-17,0) 3(-15,0) 4(-13,0) 5(-11,0) 6(-9,0) 7(-7,0) 8(-5,0) 9(-3,0) 10(-1,0) 11(1,0) 12(3,0) 13(5,0) 14(7,0) 15(9,0) 16(11,0) 17(13,0) 18(15,0) 19(17,0) 20(19,0)
  silkscreen extent -20,-1 20,1
HDR2X20-2MM [mm] "2mm 2x20 header"
  rect 1.3x1.3 hole 0.8: 1(-19,-1)
  round 1.3 hole 0.8: 2(-19,1) 3(-17,-1) 4(-17,1) 5(-15,-1) 6(-15,1) 7(-13,-1) 8(-13,1) 9(-11,-1) 10(-11,1) 11(-9,-1) 12(-9,1) 13(-7,-1) 14(-7,1) 15(-5,-1) 16(-5,1) 17(-3,-1) 18(-3,1) 19(-1,-1) 20(-1,1) 21(1,-1) 22(1,1) 23(3,-1) 24(3,1) 25(5,-1) 26(5,1) 27(7,-1) 28(7,1) 29(9,-1) 30(9,1) 31(11,-1) 32(11,1) 33(13,-1) 34(13,1) 35(15,-1) 36(15,1) 37(17,-1) 38(17,1) 39(19,-1) 40(19,1)
  silkscreen extent -20,-2 20,2
JSO-0515-01 [mm]
  round 0 hole 6.35 unplated: 1(0,0)
M2-CONNECTOR_M-KEYING [mm] "M-2 Connector, 67-pin, M Keying"
  rect 1.2x2.75 smd mask+0.051: 1(-10.35,4.5) 1(10.35,4.5)
  rect 0.3x1.55 smd mask+0.051: 1(-9.25,5.275) 2(-9,-2.275) 3(-8.75,5.275) 4(-8.5,-2.275) 5(-8.25,5.275) 6(-8,-2.275) 7(-7.75,5.275) 8(-7.5,-2.275) 9(-7.25,5.275) 10(-7,-2.275) 11(-6.75,5.275) 12(-6.5,-2.275) 13(-6.25,5.275) 14(-6,-2.275) 15(-5.75,5.275) 16(-5.5,-2.275) 17(-5.25,5.275) 18(-5,-2.275) 19(-4.75,5.275) 20(-4.5,-2.275) 21(-4.25,5.275) 22(-4,-2.275) 23(-3.75,5.275) 24(-3.5,-2.275) 25(-3.25,5.275) 26(-3,-2.275) 27(-2.75,5.275) 28(-2.5,-2.275) 29(-2.25,5.275) 30(-2,-2.275) 31(-1.75,5.275) 32(-1.5,-2.275) 33(-1.25,5.275) 34(-1,-2.275) 35(-0.75,5.275) 36(-0.5,-2.275) 37(-0.25,5.275) 38(0,-2.275) 39(0.25,5.275) 40(0.5,-2.275) 41(0.75,5.275) 42(1,-2.275) 43(1.25,5.275) 44(1.5,-2.275) 45(1.75,5.275) 46(2,-2.275) 47(2.25,5.275) 48(2.5,-2.275) 49(2.75,5.275) 50(3,-2.275) 51(3.25,5.275) 52(3.5,-2.275) 53(3.75,5.275) 54(4,-2.275) 55(4.25,5.275) 56(4.5,-2.275) 57(4.75,5.275) 58(5,-2.275) 67(7.25,5.275) 68(7.5,-2.275) 69(7.75,5.275) 70(8,-2.275) 71(8.25,5.275) 72(8.5,-2.275) 73(8.75,5.275) 74(9,-2.275) 75(9.25,5.275)
  round 1.1 hole 1.1 unplated paste+0: MH(-10,0)
  round 1.6 hole 1.6 unplated paste+0: MH(10,0)
  silkscreen extent -11,-2.55 11,5.3
MOLEX-67800-5005 [mm]
  rect 0.9x2.4 smd: 1(3.955,0.55) 2(2.685,0.55) 3(1.415,0.55) 4(0.145,0.55) 5(-1.125,0.55) 6(-2.395,0.55) 7(-3.665,0.55)
  round 2.5 hole 1.35: MH(-6.415,0.45) MH(6.415,-0.55)
  silkscreen extent -8.65,-3.9 8.6,2.85
MTG-3.2/6.5-PTH [mm] "Mounting hole, 3.2mm ID, 6.5mm OD, plated"
  round 6.5 hole 3.2: 1(0,0)
okLogo-23x5 [mm] "Opal Kelly silkscreen logo (23mm x 5mm)"
  silkscreen extent -0.09,-2.1 6.75,2.1
OSC_SMD_5X32 [mm]
  rect 0.64x1.1 smd: 1(-1.27,-1.15) 2(0,-1.15) 3(1.27,-1.15) 4(1.27,1.15) 5(0,1.15) 6(-1.27,1.15)
  silkscreen extent -2.55,-1.9 2.55,1.6
OSC_SMD_25x20 [mm]
  rect 0.65x0.85 smd: 1(-0.825,-0.775) 3(0.825,-0.775) 4(0.825,0.775) 6(-0.825,0.775)
  rect 0.25x0.85 smd: 2(0,-0.775) 5(0,0.775)
  silkscreen extent -1.35,-1.3 1.35,0.95
PVQFN-48 [mm]
  rect 0.7x0.3 smd mask+0.051: 1(-3.35,2.75) 2(-3.35,2.25) 3(-3.35,1.75) 4(-3.35,1.25) 5(-3.35,0.75) 6(-3.35,0.25) 7(-3.35,-0.25) 8(-3.35,-0.75) 9(-3.35,-1.25) 10(-3.35,-1.75) 11(-3.35,-2.25) 12(-3.35,-2.75) 25(3.35,-2.75) 26(3.35,-2.25) 27(3.35,-1.75) 28(3.35,-1.25) 29(3.35,-0.75) 30(3.35,-0.25) 31(3.35,0.25) 32(3.35,0.75) 33(3.35,1.25) 34(3.35,1.75) 35(3.35,2.25) 36(3.35,2.75)
  rect 0.3x0.7 smd mask+0.051: 13(-2.75,-3.35) 14(-2.25,-3.35) 15(-1.75,-3.35) 16(-1.25,-3.35) 17(-0.75,-3.35) 18(-0.25,-3.35) 19(0.25,-3.35) 20(0.75,-3.35) 21(1.25,-3.35) 22(1.75,-3.35) 23(2.25,-3.35) 24(2.75,-3.35) 37(2.75,3.35) 38(2.25,3.35) 39(1.75,3.35) 40(1.25,3.35) 41(0.75,3.35) 42(0.25,3.35) 43(-0.25,3.35) 44(-0.75,3.35) 45(-1.25,3.35) 46(-1.75,3.35) 47(-2.25,3.35) 48(-2.75,3.35)
  rect 4.08x4.08 smd mask+0.051: PAD(0,0)
  silkscreen extent -3.89,-3.6 3.6,3.89
QSE-020-01-X-D-A-L [mil] "0.80mm, 40 pin Surface Mount connectors with Ground Strip"
  rect 100x17 smd paste+0: 0(-317.45,0) 0(317.55,0)
  rect 185x17 smd paste+0: 0(-124.95,0) 0(125.05,0)
  rect 16x89.5 smd paste+0: 1(-299.25,-112.8) 2(-299.25,112.8) 3(-267.75,-112.8) 4(-267.75,112.8) 5(-236.25,-112.8) 6(-236.25,112.8) 7(-204.75,-112.8) 8(-204.75,112.8) 9(-173.25,-112.8) 10(-173.25,112.8) 11(-141.75,-112.8) 12(-141.75,112.8) 13(-110.25,-112.8) 14(-110.25,112.8) 15(-78.75,-112.8) 16(-78.75,112.8) 17(-47.25,-112.8) 18(-47.25,112.8) 19(-15.75,-112.8) 20(-15.75,112.8) 21(15.75,-112.8) 22(15.75,112.8) 23(47.25,-112.8) 24(47.25,112.8) 25(78.75,-112.8) 26(78.75,112.8) 27(110.25,-112.8) 28(110.25,112.8) 29(141.75,-112.8) 30(141.75,112.8) 31(173.25,-112.8) 32(173.25,112.8) 33(204.75,-112.8) 34(204.75,112.8) 35(236.25,-112.8) 36(236.25,112.8) 37(267.75,-112.8) 38(267.75,112.8) 39(299.25,-112.8) 40(299.25,112.8)
  round 47.24 hole 31.5 paste+0: MH(-479.48,-19.69) MH(479.58,-19.69)
  round 40.16 hole 40.16 unplated paste+0: MH(-396.25,105) MH(396.35,105)
  silkscreen extent -528,-146 528,146
QSFP28_RECEPTACLE_SFF-8679 [mm]
  rect 0.35x1.8 smd: 1(1.4,7.37) 2(2.2,7.37) 3(3,7.37) 4(3.8,7.37) 5(4.6,7.37) 6(5.4,7.37) 7(6.2,7.37) 8(7,7.37) 9(7.8,7.37) 10(8.6,7.37) 11(9.4,7.37) 12(10.2,7.37) 13(11,7.37) 14(11.8,7.37) 15(12.6,7.37) 16(13.4,7.37) 17(14.2,7.37) 18(15,7.37) 19(15.8,7.37) 20(15.4,9.88) 21(14.6,9.88) 22(13.8,9.88) 23(13,9.88) 24(12.2,9.88) 25(11.4,9.88) 26(10.6,9.88) 27(9.8,9.88) 28(9,9.88) 29(8.2,9.88) 30(7.4,9.88) 31(6.6,9.88) 32(5.8,9.88) 33(5,9.88) 34(4.2,9.88) 35(3.4,9.88) 36(2.6,9.88) 37(1.8,9.88) 38(1,9.88)
  round 1.55 hole 1.55 unplated: MH(0,0) MH(16.8,0)
  L1-TOP keep-out region: -0.5,-3.16 0.5,-3.16 0.5,-2.16 -0.5,-2.16
  L1-TOP keep-out region: 16.3,-3.16 17.3,-3.16 17.3,-2.16 16.3,-2.16
  silkscreen extent -0.8,-3 17.6,9.7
